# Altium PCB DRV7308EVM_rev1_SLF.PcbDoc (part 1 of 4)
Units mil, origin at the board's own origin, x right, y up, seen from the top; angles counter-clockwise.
Board outline 6187 x 6000 mil, 4 copper layers (Top Layer, Ground, Power, Bottom Layer), stack 61.2 mil thick; 306 components, 128 nets, 676 pads, 1026 vias.
Unrouted connection lines stored in the file: 208.
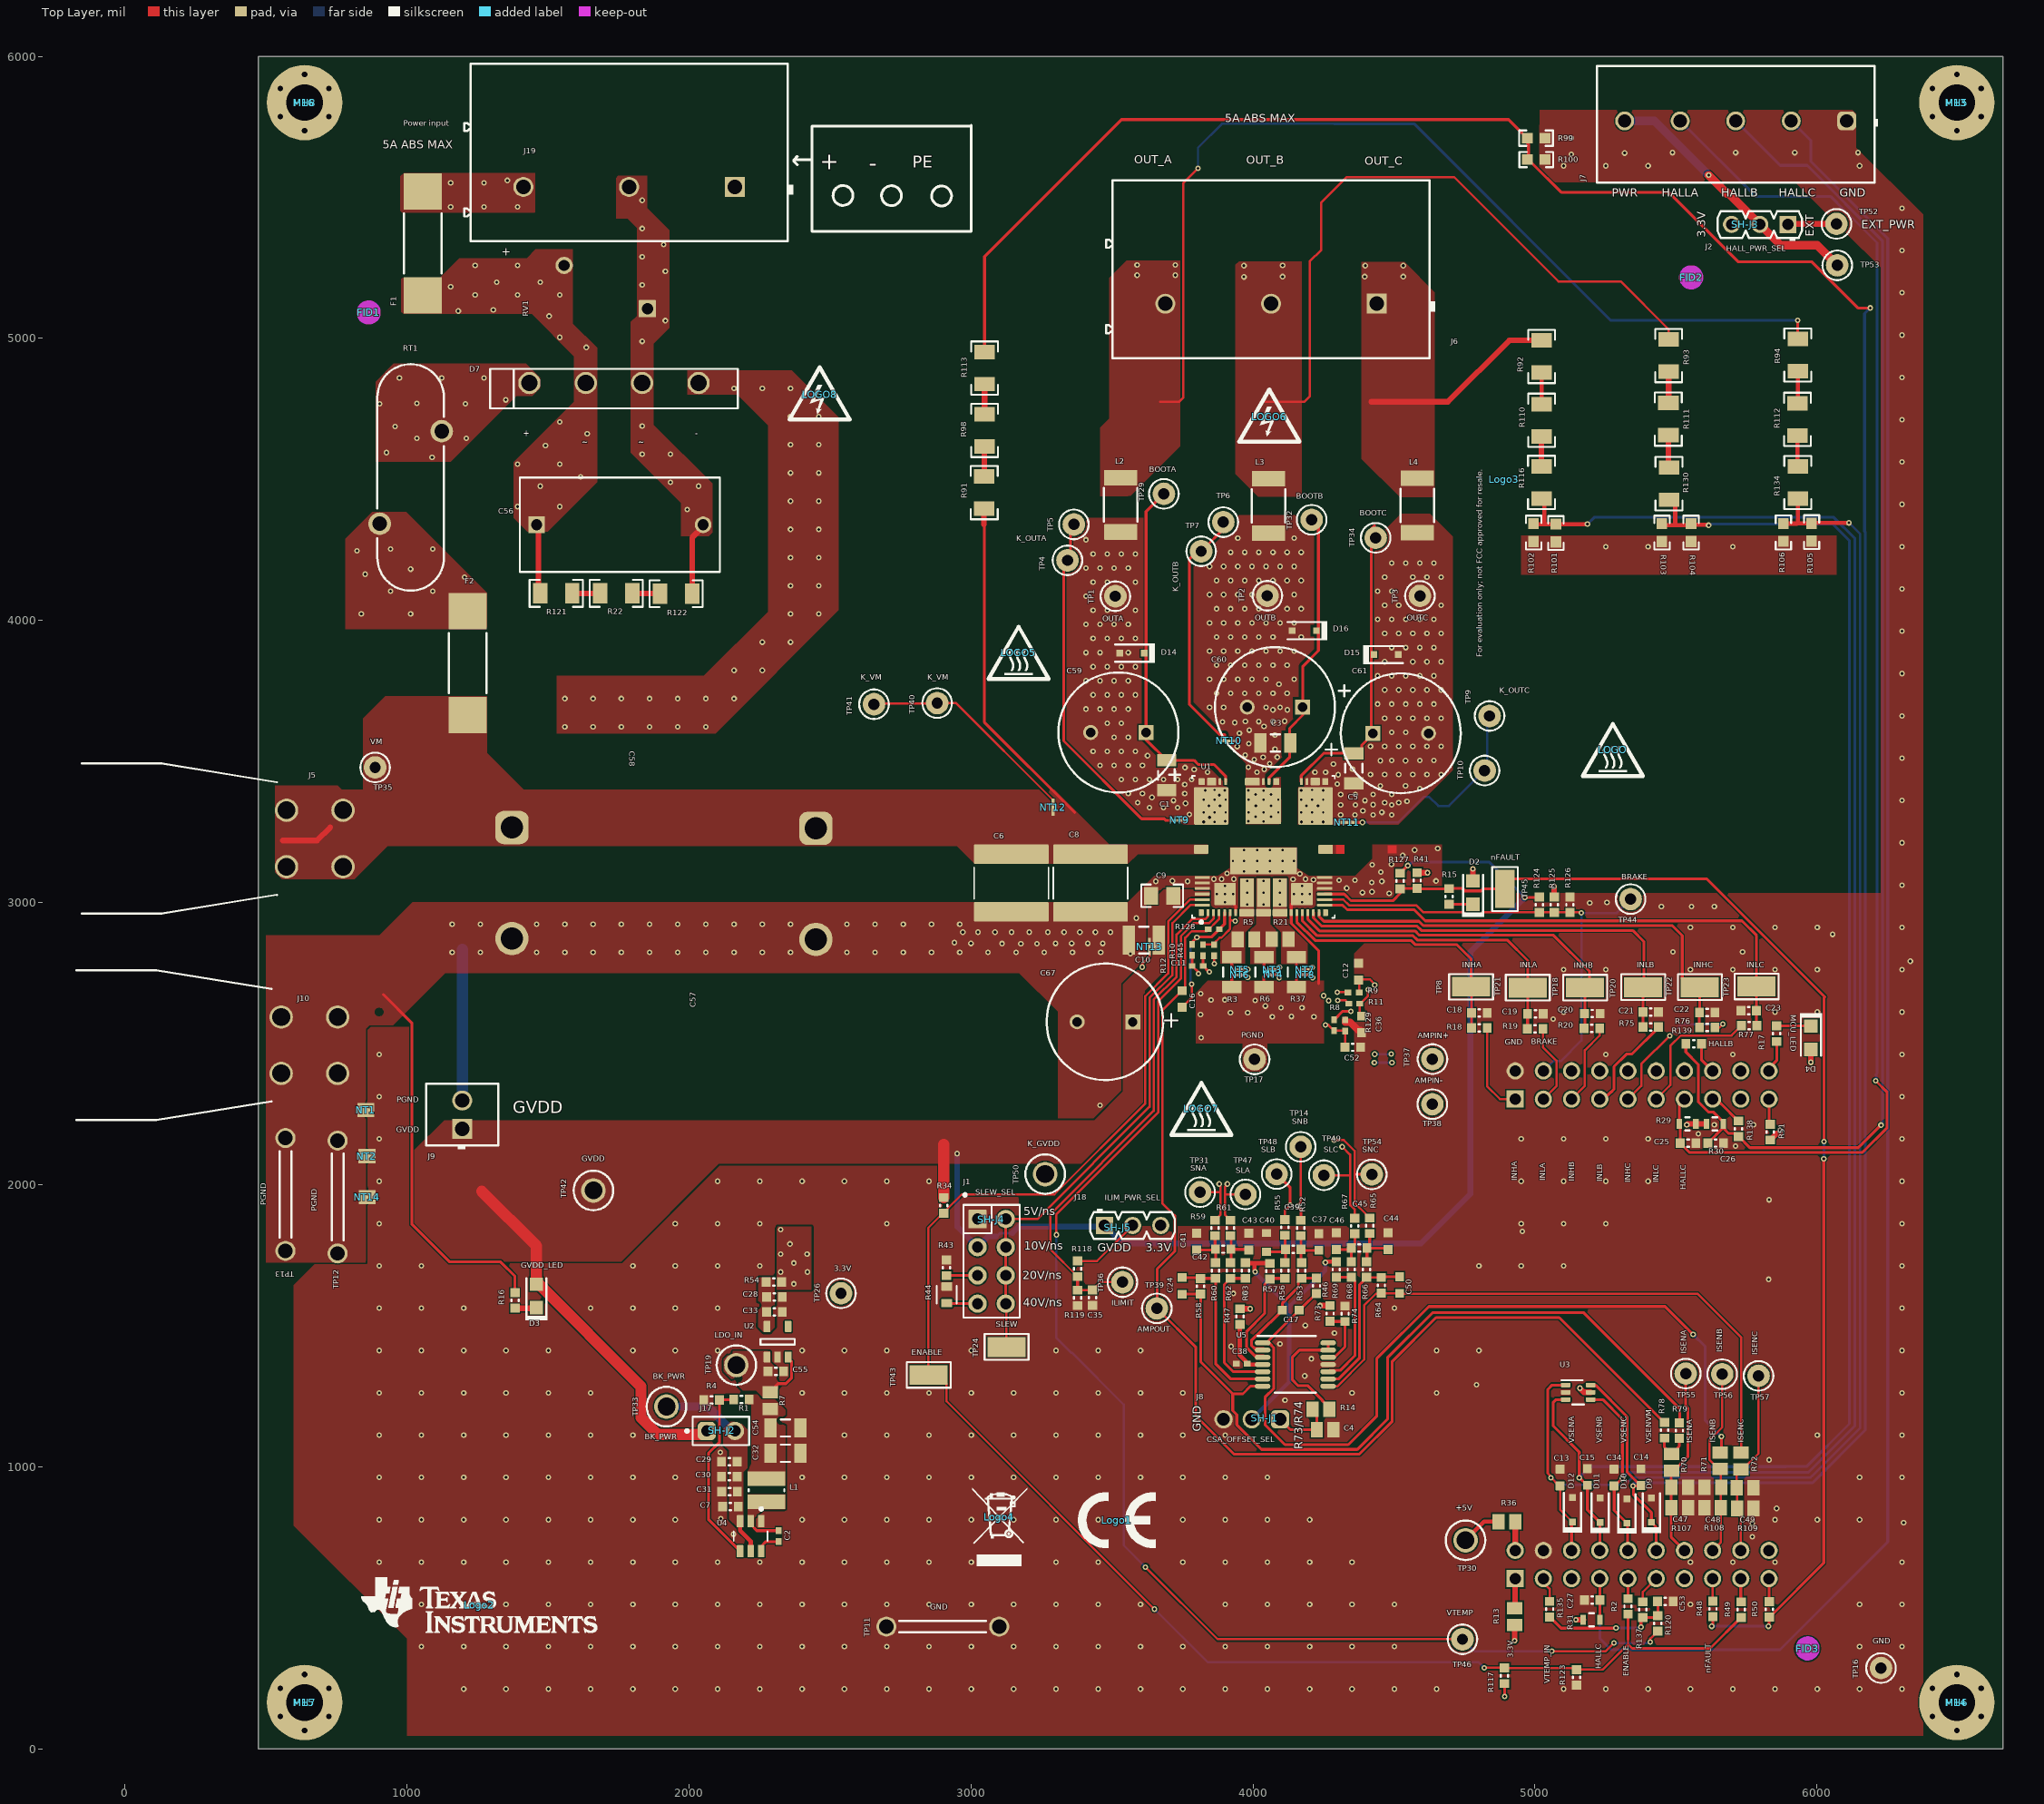
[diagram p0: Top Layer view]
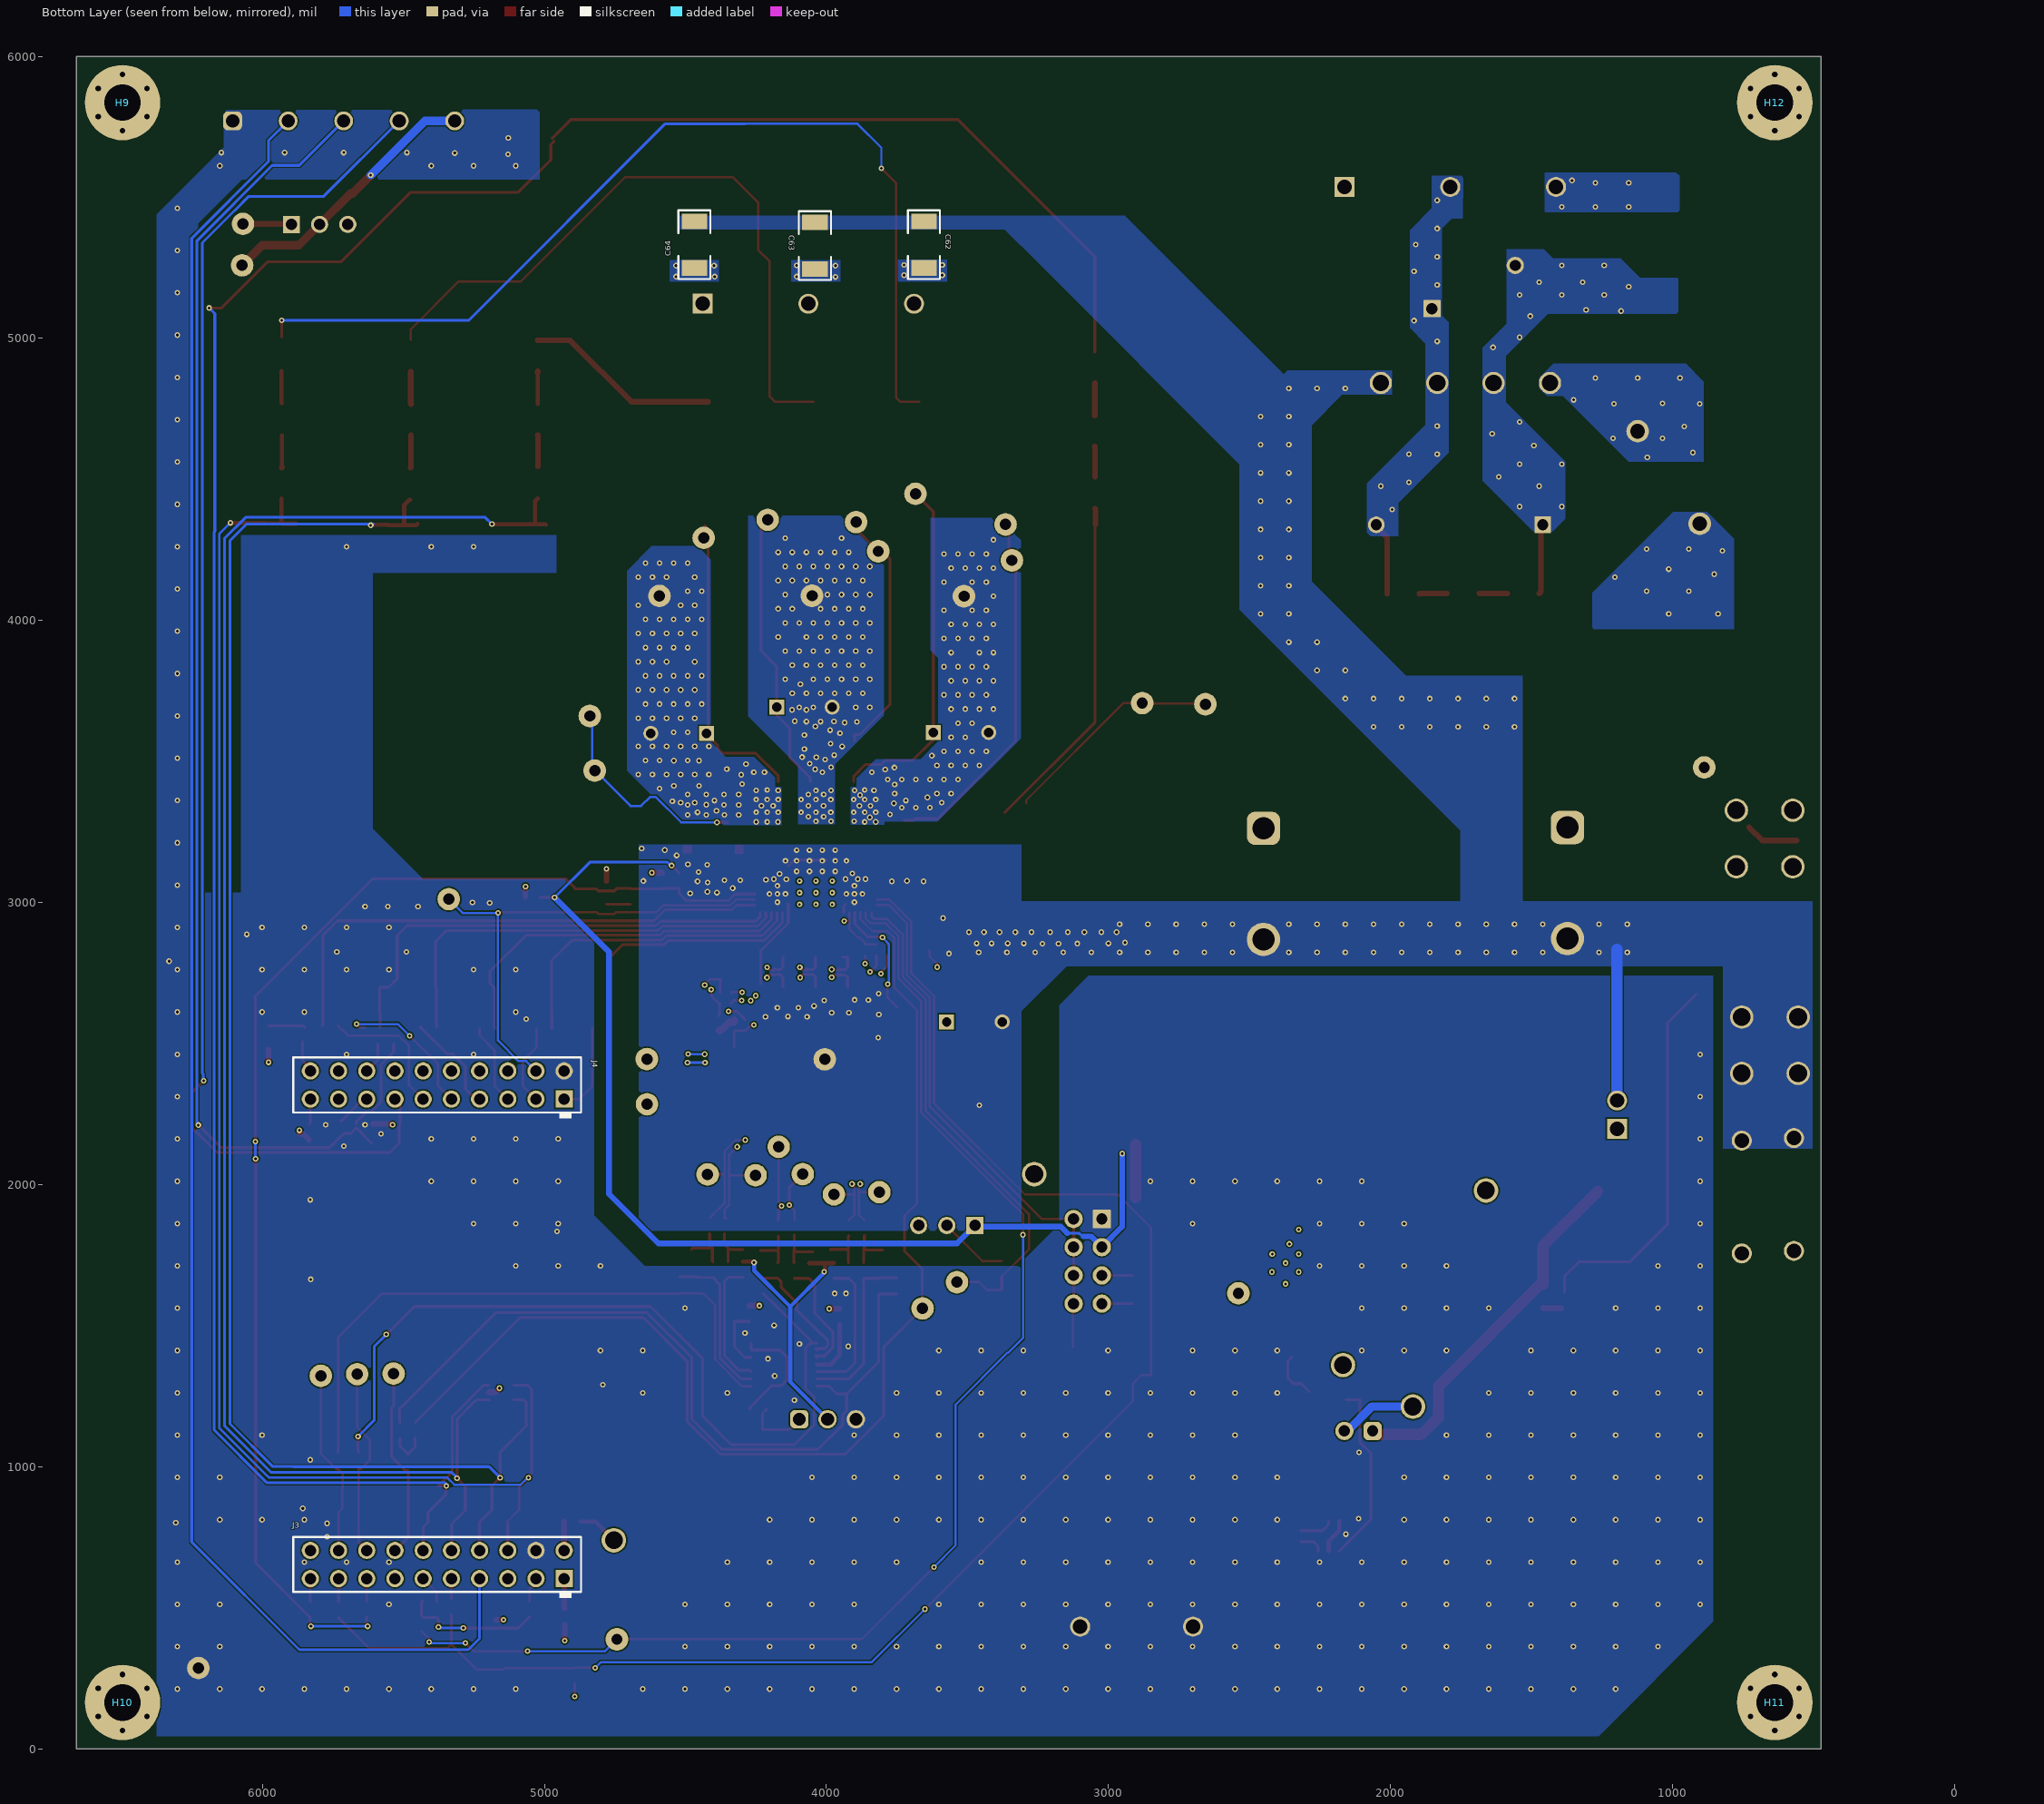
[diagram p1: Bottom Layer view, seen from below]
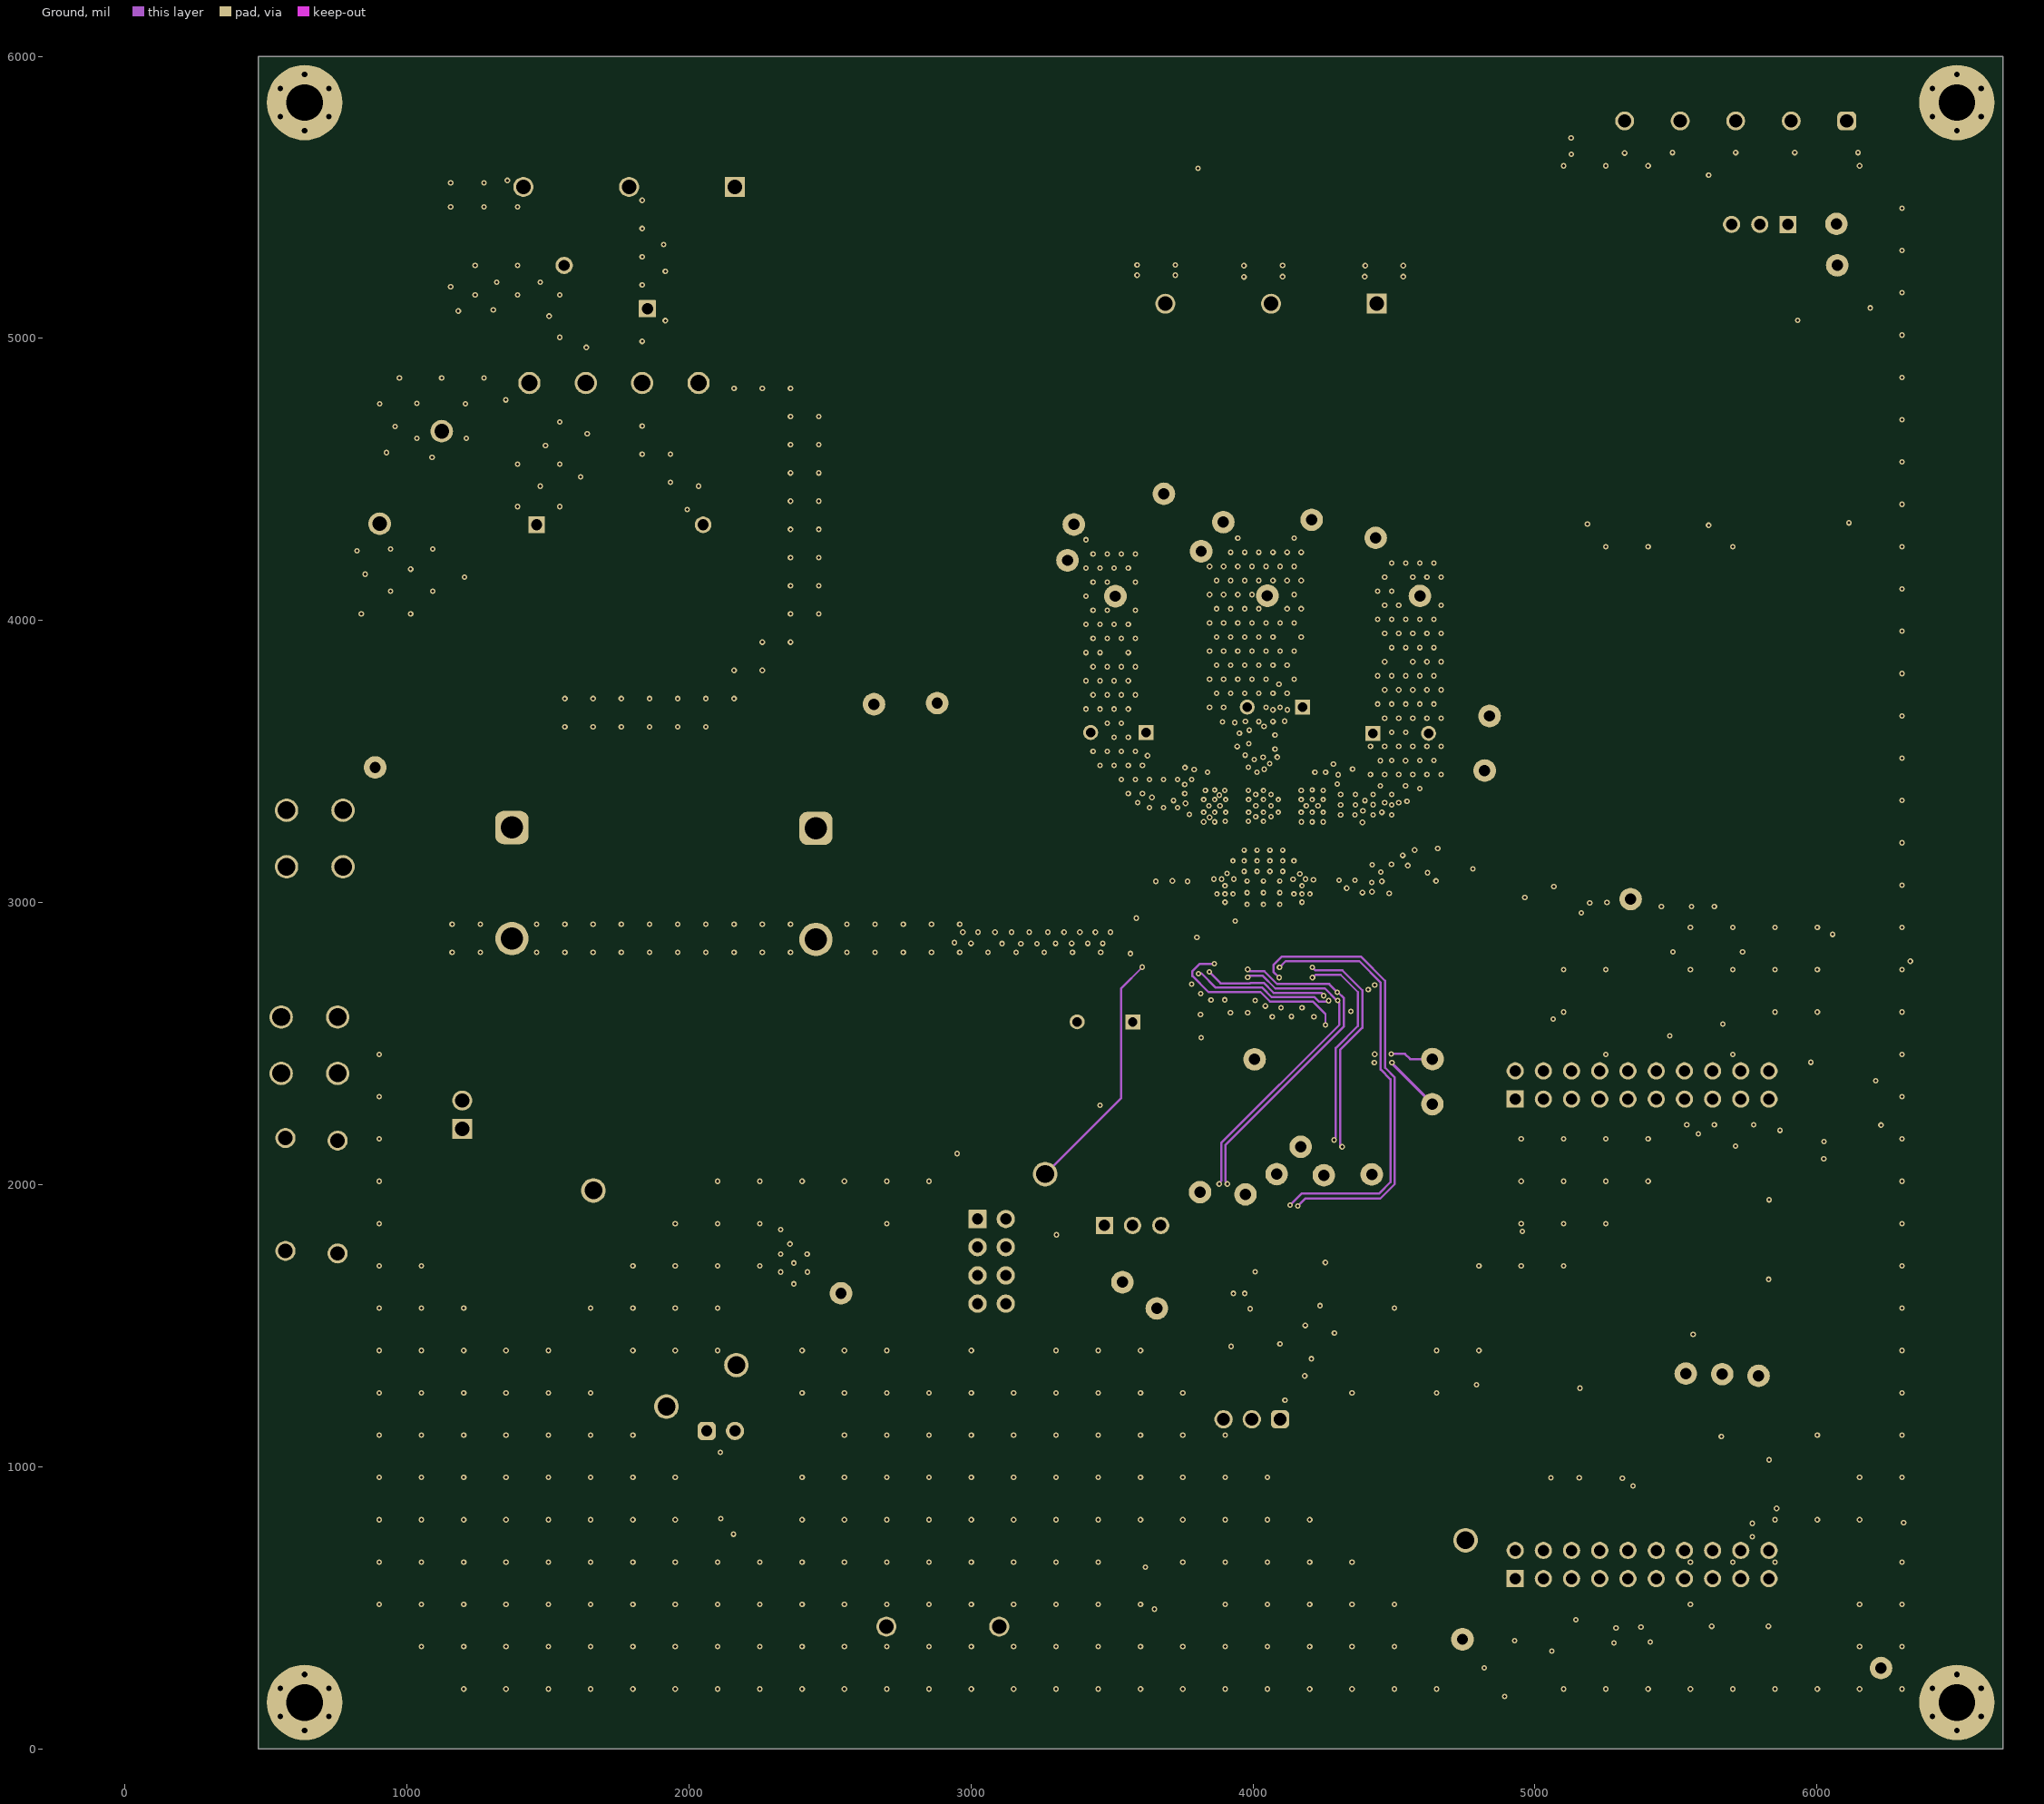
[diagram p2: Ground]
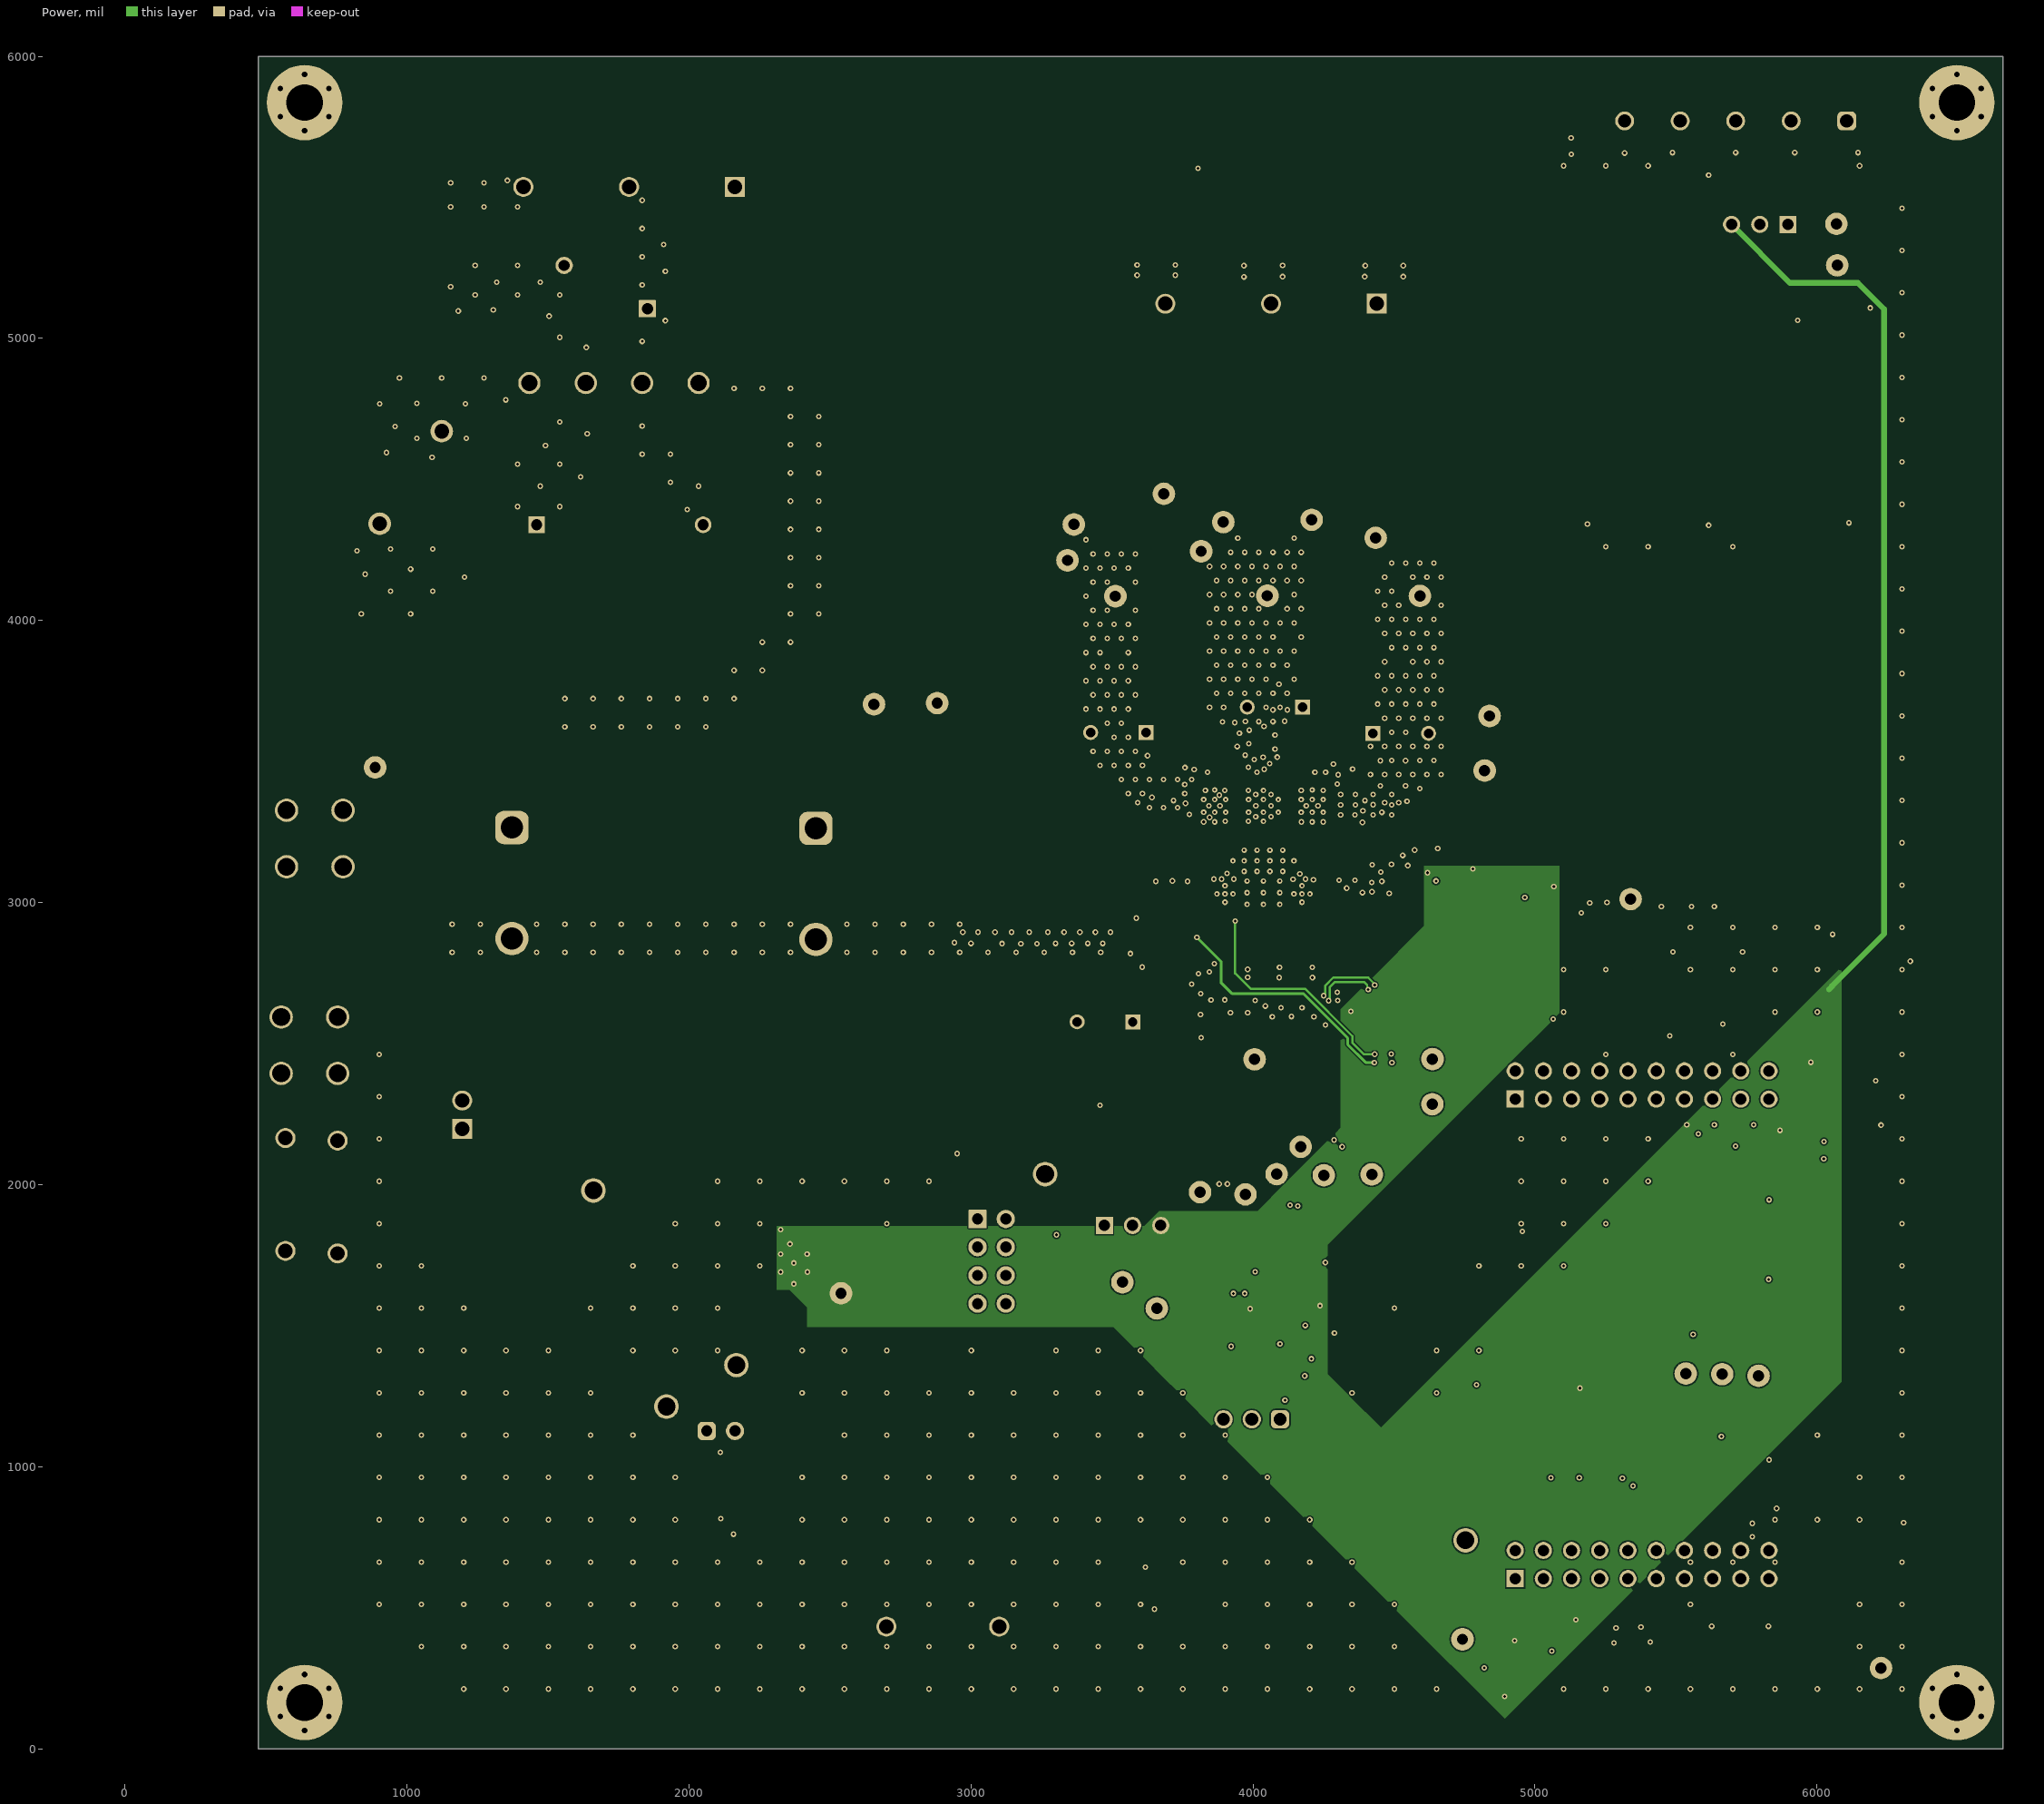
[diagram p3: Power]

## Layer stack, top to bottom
Top Solder: solder mask 0.4, Solder Resist, Dk 3.5
Top Layer: signal copper 4.2
Dielectric 1: prepreg 8, FR-4 High Tg, Dk 4.2
Ground: signal copper 1.4
Dielectric 2: core 34, FR-4 High Tg, Dk 4.2
Power: signal copper 1.4
Dielectric 3: prepreg 8, FR-4 High Tg, Dk 4.2
Bottom Layer: signal copper 4.2
Bottom Solder: solder mask 0.4, Solder Resist, Dk 3.5

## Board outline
473,0 6660,0 6660,6000 473,6000

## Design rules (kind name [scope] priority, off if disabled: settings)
AcuteAngle [All] p1: minimum=4.50000000000000E+0001 checktracksonly=FALSE
AssemblyTestPointUsage [All] p1: valid=2
BoardOutlineClearance BoardOutlineClearance_MountingHoles [OnCopper and InComponentClass('Mounting Holes')] p1: gap=39.37 ignorepadtopadclearanceinfootprint=FALSE
BoardOutlineClearance BoardOutlineClearance_Poly [OnCopper and IsPoly] p2: gap=25 ignorepadtopadclearanceinfootprint=FALSE
BoardOutlineClearance [OnCopper and Not InComponentClass('Logo') and not InComponentClass('FiducialMark') and not InRegion(1000,500,4000,800) and not InPoly] p3: gap=30 ignorepadtopadclearanceinfootprint=FALSE
Clearance Clearance_3 [InNamedPolygon('TOP_LAYER_OUTB_P018')] p1: gap=10 ignorepadtopadclearanceinfootprint=TRUE except(0: Arc-Hole Track-Hole SMDPad-Hole THPad-Hole Via-Hole Fill-Hole Poly-Hole Region-Hole Text-Hole)
Clearance "Stitching AGND" [IsStitchingVia and InNet('AGND') vs (IsVia and (Not IsStitchingVia)) Or IsPad] p2: gap=70 ignorepadtopadclearanceinfootprint=TRUE
Clearance Clearance_Keepouts [((IsTrack Or IsArc) And Not InPoly) And IsFree and IsKeepOut vs ((IsTrack Or IsArc) And Not InPoly) And IsFree and IsKeepOut] p3: gap=7 ignorepadtopadclearanceinfootprint=TRUE
Clearance Clearance_Poly [InPolygon] p4: gap=5 ignorepadtopadclearanceinfootprint=TRUE except(7: Fill-Fill Fill-Poly Fill-Region Poly-Poly Poly-Region Region-Region)
Clearance Clearance_FiducialMark [IsKeepOut and InComponentClass('FiducialMark') vs IsPad and InComponentClass('FiducialMark')] p5: gap=0 ignorepadtopadclearanceinfootprint=FALSE
Clearance [InNetClass('All Nets') vs OnLayer('Top Layer')] p6: gap=7 ignorepadtopadclearanceinfootprint=TRUE
Clearance Clearance_2 [InNetClass('All Nets') vs OnLayer('Bottom Layer')] p7: gap=9 ignorepadtopadclearanceinfootprint=TRUE
Clearance Clearance_1 [InNetClass('All Nets') vs OnLayer('Power')] p8: gap=7.46 ignorepadtopadclearanceinfootprint=TRUE
Clearance Clearance_4 [InNetClass('All Nets') vs OnLayer('Ground')] p9: gap=7.46 ignorepadtopadclearanceinfootprint=TRUE
ComponentClearance ComponentClearance_MountingHoles_FiducialMarks [InComponentClass('Mounting Holes') vs InComponentClass('FiducialMark')] p1: gap=50 collisioncheckmode=3 verticalgap=10 showdistances=FALSE
ComponentClearance ComponentClearance_Shunt [InComponentClass('Header') vs InComponentClass('Shunt')] p2: gap=0 collisioncheckmode=3 verticalgap=0 showdistances=FALSE
ComponentClearance ComponentClearance_Logo [InComponentClass('Logo')] p3: gap=50 collisioncheckmode=3 verticalgap=10 showdistances=FALSE
ComponentClearance ComponentClearance_ScrewToNut [(HasFootprint('NY PMS 440 0025 PH')) vs (HasFootprint('Keystone_1902C'))] p4: gap=5 collisioncheckmode=3 verticalgap=10 showdistances=FALSE
ComponentClearance ComponentClearance_MountingHoles [InComponentClass('Mounting Holes')] p5: gap=250 collisioncheckmode=3 verticalgap=100000 showdistances=FALSE
ComponentClearance ComponentClearance_SmallPassives [HasFootprint('0201*') or HasFootprint('0402*') or HasFootprint('0508') or HasFootprint('0603*') or HasFootprint('0612') or HasFootprint('0805*') or HasFootprint('0815*') or HasFootprint('0830*') or HasFootprint('1206*') or HasFootprint('1210*') or HasFootprint('1808*') or HasFootprint('1812*') or HasFootprint('1825*') or HasFootprint('2010*') or HasFootprint('2220*') or HasFootprint('2225*') or HasFootprint('2512*') or HasFootprint('2728*') or HasFootprint('3518*') vs HasFootprint('0201*') or HasFootprint('0402*') or HasFootprint('0508') or HasFootprint('0603*') or HasFootprint('0612') or HasFootprint('0805*') or HasFootprint('0815*') or HasFootprint('0830*') or HasFootprint('1206*') or HasFootprint('1210*') or HasFootprint('1808*') or HasFootprint('1812*') or HasFootprint('1825*') or HasFootprint('2010*') or HasFootprint('2220*') or HasFootprint('2225*') or HasFootprint('2512*') or HasFootprint('2728*') or HasFootprint('3518*')] p6: gap=14.96 collisioncheckmode=3 verticalgap=10 showdistances=FALSE
ComponentClearance ComponentClearance_THtoSMT [IsThruComponent vs IsSMTComponent] p7: gap=40 collisioncheckmode=3 verticalgap=30 showdistances=FALSE
ComponentClearance ComponentClearance_THtoTH [IsThruComponent vs IsThruComponent] p8: gap=30 collisioncheckmode=3 verticalgap=30 showdistances=FALSE
ComponentClearance [All] p9: gap=30 collisioncheckmode=3 verticalgap=10 showdistances=FALSE
ComponentClearance ComponentClearance_NT [(InComponent('NT1') OR InComponent('NT2') OR InComponent('NT3') OR InComponent('NT4') OR InComponent('NT5') OR InComponent('NT6')) vs InComponent('No Component')] p10: gap=0 collisioncheckmode=3 verticalgap=10 showdistances=FALSE
DiffPairsRouting [All] p1: maxlimit=100 minlimit=10 mostfreqgap=10 toplayer_minwidth=15 toplayer_maxwidth=15 toplayer_prefwidth=15 midlayer1_minwidth=15 midlayer1_maxwidth=15 midlayer1_prefwidth=15 midlayer2_minwidth=15 midlayer2_maxwidth=15 midlayer2_prefwidth=15 bottomlayer_minwidth=15 bottomlayer_maxwidth=15 bottomlayer_prefwidth=15 maxuncoupledlength=1000
FabricationTestPointUsage TestPointUsage [All] p1: valid=2 allowmultiple=FALSE
FabricationTestpoint Testpoint [All] p1: side=3 testpointundercomponent=TRUE minsize=40 maxsize=100 preferedsize=60 minholesize=0 maxholesize=40 preferedholesize=32 testpointgrid=1 allowsidetop=TRUE allowsidebottom=TRUE usegrid=TRUE gridtolerance=0.01
FanoutControl Fanout_LCC [IsLCC] p1: bgadir=Out bgaviamode=Centered fanoutstyle=Auto fanoutdirection=Alternating viagrid=1 // Fanout_LCC (Default Rule)
FanoutControl Fanout_BGA [IsBGA] p2: bgadir=Out bgaviamode=Centered fanoutstyle=Auto fanoutdirection=Alternating viagrid=1 // Fanout_BGA (Default Rule)
FanoutControl Fanout_Default [All] p4: bgadir=Out bgaviamode=Centered fanoutstyle=Auto fanoutdirection=Alternating viagrid=1 // Fanout_Default (Default Rule)
FanoutControl Fanout_Small [(CompPinCount < 5)] p5: bgadir=Out bgaviamode=Centered fanoutstyle=Auto fanoutdirection=OutThenIn viagrid=1 // Fanout_Small (Default Rule)
Height [All] p1: minheight=0 maxheight=1270 prefheight=500
HoleSize [All] p1: absolutevalues=TRUE maxlimit=270 minlimit=1 maxpercent=80.000 minpercent=20.000
MinimumAnnularRing MinimumAnnularRing_ThermalPadVias [IsVia and InAnyComponent] p1: minimumring=5
MinimumAnnularRing [All] p2: minimumring=5
MinimumSolderMaskSliver MinimumSolderMaskSliver_Logo [InComponentClass('Logo') vs InComponentClass('Logo')] p1: minsoldermaskwidth=0.7
MinimumSolderMaskSliver [All] p2: minsoldermaskwidth=1
PlaneConnect [All] p1: planeconnectstyle=Direct reliefexpansion=10 reliefentries=4 reliefconductorwidth=10 reliefairgap=10
PolygonConnect "direct connect OUTB" [All vs IsNamedPolygon('TOP_LAYER_OUTB_P018')] p1: connectstyle=Direct reliefconductorwidth=10 reliefentries=4 polygonreliefangle="90 Angle" airgapwidth=10
PolygonConnect OUTB_POLY [All vs IsNamedPolygon('TOP_LAYER_OUTB_P018')] p2: connectstyle=Direct reliefconductorwidth=10 reliefentries=4 polygonreliefangle="90 Angle" airgapwidth=10
PolygonConnect PolygonConnect_1 [All vs IsNamedPolygon('TOP_LAYER_OUTB_P018')] p3: connectstyle=Direct reliefconductorwidth=10 reliefentries=4 polygonreliefangle="90 Angle" airgapwidth=10
PolygonConnect [All] p4: connectstyle=Direct reliefconductorwidth=10 reliefentries=4 polygonreliefangle="90 Angle" airgapwidth=10
RoutingVias ThermalPadVias [IsVia and InAnyComponent] p1: holewidth=7.87 width=19.68 viastyle="Through Hole" minholewidth=7.87 minwidth=19.68 maxholewidth=30 maxwidth=50
RoutingVias [All] p2: holewidth=10 width=25 viastyle="Through Hole" minholewidth=10 minwidth=20 maxholewidth=10 maxwidth=30
SilkToBoardRegionClearance [Not ((IsComment or IsDesignator) And (Hide <> 'False')) and not InRegion(1000,500,4000,800)] p1:
SilkToSilkClearance SilkToSilkClearance_Pb-FreeLogo [(HasFootprint('Pb-Free_Overlay_Medium') OR HasFootprint('Pb-Free_Overlay_Small')) vs (HasFootprint('Pb-Free_Overlay_Medium') OR HasFootprint('Pb-Free_Overlay_Small'))] p1: silktosilkclearance=1
SilkToSilkClearance [All] p2: silktosilkclearance=1
SilkToSolderMaskClearance [IsPad] p1: minsilkscreentomaskgap=1 clearancetoexposedcopper=TRUE
SolderMaskExpansion [All] p1: expansion=1.97 istentingtop=FALSE
UnRoutedNet [All] p1: checkbadconnections=TRUE
Width [All] p1: maxlimit=100 minlimit=6 preferedwidth=10 checkconnectedcopper=TRUE
13 further rules are at their usual default settings.

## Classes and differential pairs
component class Screw: H13 H14 H15 H16
net class High_Voltage: OUTA OUTC VM
component class DRV7308EVM_rev1_POWER_AND_CONNECTORS_SLF: C4 C13 C14 C15 C17 C24 C25 C26 C27 C34 C35 C37 C38 C39 C40 C41 C42 C43 C44 C45 C46 C47 C48 C49 C50 C56 C57 C58 C62 C63 C64 D7 D9 D10 D11 D12 F1 F2 HALL_PWR J1 J2 J5 J6 J7 J8 J9 J10 J18 J19 L2 L3 L4 NT1 NT2 NT13 NT14 R14 R22 R29 R30 R31 R43 R44 R46 R47 R52 R53 R55 R56 R57 R58 R59 R60 R61 R62 R63 R64 R65 R66 R67 R68 R69 R70 R71 R72 R73 R74 R78 R79 R91 R92 R93 R94 R98 R99 R100 R101 R102 R103 R104 R105 R106 R107 R108 R109 R110 R111 R112 R113 R116 R118 R119 R121 R122 R130 R134 RT1 RV1 SH-J1 SH-J3 SH-J4 SH-J5 TP11 TP12 TP13 TP14 TP16 TP17 TP31 TP42 TP50 TP52 TP53 TP54 TP55 TP56 TP57 U3 U5
component class Shunt: SH-J1 SH-J2 SH-J3 SH-J4 SH-J5
component class DRV7308EVM_rev1_DRIVER_SLF: 40 C1 C2 C3 C5 C6 C7 C8 C9 C10 C11 C12 C16 C18 C19 C20 C21 C22 C23 C28 C29 C30 C31 C32 C33 C36 C52 C53 C54 C55 C59 C60 C61 C67 D2 D3 D4 D14 D15 D16 D? J3 J4 J17 L1 NT3 NT4 NT5 NT6 NT7 NT8 NT9 NT10 NT11 NT12 R1 R2 R3 R4 R5 R6 R7 R8 R9 R10 R11 R12 R13 R15 R16 R17 R18 R19 R20 R21 R34 R36 R37 R41 R45 R48 R49 R50 R51 R54 R75 R76 R77 R117 R120 R123 R124 R125 R126 R127 R128 R129 R135 R137 R138 R139 SH-J2 TP1 TP2 TP3 TP4 TP5 TP6 TP7 TP8 TP9 TP10 TP18 TP19 TP20 TP21 TP22 TP23 TP24 TP26 TP29 TP30 TP32 TP33 TP34 TP35 TP36 TP37 TP38 TP39 TP40 TP41 TP43 TP44 TP45 TP46 TP47 TP48 TP49 U1 U2 U4
component class Header: J1 J2 J8 J17 J18
component class Logo: Logo2
component class DRV7308EVM_rev1_HARDWARE_SLF: FID1 FID2 FID3 H9 H10 H11 H12 H13 H14 H15 H16 LOGO Logo1 Logo2 Logo3 Logo4 LOGO5 LOGO6 LOGO7 LOGO8 MH5 MH6 MH7 MH8 ZZ1 ZZ2 ZZ3 ZZ4
component class FiducialMark: FID1 FID2 FID3
component class AssemblyNote: ZZ1 ZZ2 ZZ3 ZZ4

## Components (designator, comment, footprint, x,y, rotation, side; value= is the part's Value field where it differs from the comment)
C1 "12063C105KAT2A" 1206L 3694,3451 r90 top value=1uF
C2 "CL05B104KP5NNNC" 0402L 2318,753.76 r270 top value=0.1uF
C3 "12063C105KAT2A" 1206L 4079,3566 r0 top value=1uF
C4 "C0805C471K5RACTU" 0805L 4256,1131 r0 top value=470pF
C5 "12063C105KAT2A" 1206L 4357,3476 r90 top value=1uF
C6 "VJ2225Y104KXGAT" FP-VJ2225Y104KXGAT_2225-IPC_A 3143,3069 r90 top value=100nF
C7 "885012206095" 0603L 2147,858.44 r180 top value=0.1uF
C8 "VJ2225Y104KXGAT" FP-VJ2225Y104KXGAT_2225-IPC_A 3424,3068.81 r90 top value=100nF
C9 "08053C104KAT2A" 0805_HV 3678,3024 r0 top value=0.1uF
C10 "GRM32ER71E226KE15L" 1210_270L 3613,2867 r0 top value=22uF
C11 "CL05B103KA5NNNC" 0402L 3804,2775 r180 top value=0.01uF
C12 "885012206003" WCAP-CSGP_0603_L1.6W0.8H0.8_Reflow 4374,2755 r270 top
C13 "885012206069" FP-885012206069_0603-MFG 5089,961.53 r270 top
C14 "885012206069" FP-885012206069_0603-MFG 5376,962.53 r270 top
C15 "885012206069" FP-885012206069_0603-MFG 5186,963.53 r270 top
C16 "885012206003" WCAP-CSGP_0603_L1.6W0.8H0.8_Reflow 3749,2658 r90 top
C17 "885012206003" WCAP-CSGP_0603_L1.6W0.8H0.8_Reflow 4134,1555 r0 top
C18 "885012206083" 0603L 4802.59,2608.59 r0 top value=1000pF
C19 "885012206083" 0603L 5001.36,2605.29 r0 top value=1000pF
C20 "885012206083" 0603L 5203.36,2606.29 r0 top value=1000pF
C21 "885012206083" 0603L 5410.59,2611.59 r0 top value=1000pF
C22 "885012206083" 0603L 5610.59,2609.59 r0 top value=1000pF
C23 "885012206083" 0603L 5757.61,2616.59 r180 top value=1000pF
C24 "885012206003" WCAP-CSGP_0603_L1.6W0.8H0.8_Reflow 3749,1641 r270 top
C25 "885012206034" 0603L 5542.82,2147 r0 top value=1000pF
C26 "885012206034" 0603L 5640.82,2147 r0 top value=1000pF
C27 "885012206034" 0603L 5202.82,527 r180 top value=1000pF
C28 "LMK107B7105KAHT" 0603L 2303,1601.44 r0 top value=1uF
C29 "CGA3E1X7R1E105K080AC" 0603L 2143,1017.44 r180 top value=1uF
C30 "CGA3E1X7R1E105K080AC" 0603L 2143,964.44 r180 top value=1uF
C31 "CGA3E1X7R1E105K080AC" 0603L 2144,911.44 r180 top value=1uF
C32 "C3216X7R1E106K160AB" 1206_180L 2342,1047.44 r0 top value=10uF
C33 "EMK107B7104KA-T" 0603L 2303,1548.44 r0 top value=0.1uF
C34 "885012206069" FP-885012206069_0603-MFG 5280,961.53 r270 top
C35 "885012206095" 0603L 3431,1599 r270 top value=0.1uF
C36 "885012206003" WCAP-CSGP_0603_L1.6W0.8H0.8_Reflow 4385,2568 r270 top
C37 "885012206003" WCAP-CSGP_0603_L1.6W0.8H0.8_Reflow 4234,1796.53 r270 top
C38 "C1005X5R1A225K050BC" 0402L 3960.26,1365.14 r0 top value=2.2uF
C39 "885012206034" 0603L 4142.56,1770 r180 top value=1000pF
C40 "885012206003" WCAP-CSGP_0603_L1.6W0.8H0.8_Wave 4048.26,1795.14 r90 top
C41 "885012206003" WCAP-CSGP_0603_L1.6W0.8H0.8_Reflow 3800,1798 r270 top
C42 "885012206034" 0603L 3894.26,1771.14 r0 top value=1000pF
C43 "885012206003" WCAP-CSGP_0603_L1.6W0.8H0.8_Reflow 3985,1798 r90 top
C44 "885012206003" WCAP-CSGP_0603_L1.6W0.8H0.8_Reflow 4479,1799.53 r270 top
C45 "885012206034" 0603L 4376.56,1775 r180 top value=1000pF
C46 "885012206003" WCAP-CSGP_0603_L1.6W0.8H0.8_Reflow 4296,1799.53 r90 top
C47 "C0805C471K5RACTU" 0805L 5512.82,927 r0 top value=470pF
C48 "C0805C471K5RACTU" 0805L 5630.82,927 r180 top value=470pF
C49 "C0805C471K5RACTU" 0805L 5744.82,925 r0 top value=470pF
C50 "885012206003" WCAP-CSGP_0603_L1.6W0.8H0.8_Reflow 4520,1644 r270 top
C52 "885012206095" 0603L 4354,2487 r180 top value=0.1uF
C53 "06031C103JAT2A" 0603L 5462.14,521.69 r0 top value=0.01uF
C54 "C3216X7R1E106K160AB" 1206_180L 2342,1137.44 r0 top value=10uF
C55 "LMK107B7105KAHT" 0603L 2308,1337.9 r0 top value=1uF
C56 "B32922C3334M" B32922_14.5mm 1755,4339.36 r0 top value=0.33uF
C57 "381LQ151M450J022" 381LQ_J02 2450.24,3066.15 r270 top value=150uF
C58 "381LQ151M450J022" 381LQ_J02 1372,3069 r270 top value=150uF
C59 "UBT1E221MPD1TD" BT_1000x1250 3522.57,3603 r180 top value=220uF
C60 "UBT1E221MPD1TD" BT_1000x1250 4078,3693 r180 top value=220uF
C61 "UBT1E221MPD1TD" BT_1000x1250 4524,3600 r0 top value=220uF
C62 "GR442QR73D102KW01L" 1808 3654,5332.32 r90 bottom value=1000pF
C63 "GR442QR73D102KW01L" 1808 4040.9,5329 r90 bottom value=1000pF
C64 "GR442QR73D102KW01L" 1808 4468,5332.32 r90 bottom value=1000pF
C67 "EKMG250ELL102MJ20S" Chemi-Con_1000x2000 3475,2577 r180 top value=1000uF
D2 "LTST-C170KRKT" LED_LTST-C170_Red 4780,3035.42 r270 top value=Red
D3 "GVDD_LED" LTST-C170KGKT_Green 1459,1605.34 r270 top value=Green
D4 "MCU_LED" LTST-C170KFKT_Orange 5978.28,2520.42 r90 top value=Orange
D7 "GBU606" GBU 1734,4842 r0 top value=600V
D9 "MMDL101T1G" SOD-323 5412.82,846 r90 top value=7V
D10 "MMDL101T1G" SOD-323 5325.82,843 r90 top value=7V
D11 "MMDL101T1G" SOD-323 5230.82,845.31 r90 top value=7V
D12 "MMDL101T1G" SOD-323 5132.82,847 r90 top value=7V
D14 "MMSZ5248BS-7-F" SOD-323 3570.69,3884 r180 top value=18V
D15 "MMSZ5248BS-7-F" SOD-323 4472.31,3879 r0 top value=18V
D16 "MMSZ5248BS-7-F" SOD-323 4181.69,3964 r180 top value=18V
F1 "0443003.DR" FUSE_0443 1056,5337 r90 top
F2 "0443003.DR" FUSE_0443 1215,3849 r270 top
FID1 "Fiducial" Fiducial10-20 864,5092 r0 top
FID2 "Fiducial" Fiducial10-20 5553.69,5216.5 r0 top
FID3 "Fiducial" Fiducial10-20 5966.33,355.55 r0 top
H9 "24438" Keystone24438 6496,5836 r180 bottom
H10 "24438" Keystone24438 6496,164 r180 bottom
H11 "24438" Keystone24438 637,164 r180 bottom
H12 "24438" Keystone24438 637,5836 r180 bottom
H13 "MPMS 003 0005 PH" BuildingFastener_MPMS_003_0005_PH 6496,5836 r0 top
H14 "MPMS 003 0005 PH" BuildingFastener_MPMS_003_0005_PH 6496,164 r0 top
H15 "MPMS 003 0005 PH" BuildingFastener_MPMS_003_0005_PH 637,164 r0 top
H16 "MPMS 003 0005 PH" BuildingFastener_MPMS_003_0005_PH 637,5836 r0 top
J1 "SLEW_SEL" TSW-104-07-G-D 3073.23,1728 r270 top
J2 "HALL_PWR_SEL" FCI_68001-403HLF 5797,5404 r180 top
J3 "SSQ-110-03-G-D" Samtec_SSQ-110-03-x-D 5379.82,653 r0 bottom
J4 "SSQ-110-03-G-D" Samtec_SSQ-110-03-x-D 5379.82,2353 r0 bottom
J5 "CT3151SP-2" CTE_CT3151SP-2 -171,3227 r0 top
J6 "1904150" Phoenix_1904150 4064,5245 r180 top
J7 "HALL IN" Phoenix_1792892 5711.74,5771 r180 top
J8 "CSA_OFFSET_SEL" WURTH_61300311121 3995.7,1168 r180 top
J9 "GVDD" On-Shore_OSTVN02A150 1196,2248 r90 top
J10 "CT3151SP-0" CTE_CT3151SP-0 -190,2494 r0 top
J17 "BK_PWR" TSW-102-07-G-S 2113,1126.44 r0 top
J18 "ILIM_PWR_SEL" FCI_68001-403HLF 3573,1855 r0 top
J19 "Power input" Phoenix_1904150 1787.5,5659 r180 top
L1 "78438335047" WE-MAIA_3015 2275,916.44 r90 top value=4.7uH
L2 "742792511" 1812_170_HighSpeed 3531,4410 r90 top value="120 ohm"
L3 "742792511" 1812_170_HighSpeed 4055,4406 r90 top value="120 ohm"
L4 "742792511" 1812_170_HighSpeed 4583,4408 r90 top value="120 ohm"
LOGO "CAUTION HOT SURFACE" IEC_HotSurface_Small 5276,3541 r0 top
Logo1 "CE Mark" CE_Mark_5mm 3517,810 r0 top
Logo2 "Texas Instruments" TI_Stacked_Overlay_Small 1256,509 r0 top
Logo3 "FCC disclaimer" FCC_disclaimer 4890,4499.8 r90 top
Logo4 "WEEE logo" WEEE_Minimum 3100,820.64 r0 top
LOGO5 "CAUTION HOT SURFACE" IEC_HotSurface_Small 3169,3886 r0 top
LOGO6 "DANGER HIGH VOLTAGE" IEC_HighVoltage_Small 4058,4722 r0 top
LOGO7 "CAUTION HOT SURFACE" IEC_HotSurface_Small 3817,2269 r0 top
LOGO8 "DANGER HIGH VOLTAGE" IEC_HighVoltage_Small 2463.51,4800.51 r0 top
MH5 "MTG_Pads" MTGP_M3_PanHead 6496,5836 r0 top
MH6 "MTG_Pads" MTGP_M3_PanHead 6496,164 r0 top
MH7 "MTG_Pads" MTGP_M3_PanHead 637,164 r0 top
MH8 "MTG_Pads" MTGP_M3_PanHead 637,5836 r0 top
NT1 "Net-Tie" Net-Tie_50milWide_30milLong 854,2263.85 r180 top net-tie
NT2 "Net-Tie" Net-Tie_50milWide_30milLong 858,2101 r180 top net-tie
NT3 "Net-Tie" Net-Tie_10mil 4070,2762 r0 top net-tie
NT4 "Net-Tie" Net-Tie_10mil 4073,2745 r0 top net-tie
NT5 "Net-Tie" Net-Tie_10mil 3954,2762 r0 top net-tie
NT6 "Net-Tie" Net-Tie_10mil 3954,2743 r0 top net-tie
NT7 "Net-Tie" Net-Tie_10mil 4186,2762 r0 top net-tie
NT8 "Net-Tie" Net-Tie_10mil 4186,2744 r0 top net-tie
NT9 "Net-Tie" Net-Tie_10milWide_30milLong 3740,3292 r180 top net-tie
NT10 "Net-Tie" Net-Tie_10milWide_30milLong 3915,3573 r180 top net-tie
NT11 "Net-Tie" Net-Tie_10milWide_30milLong 4334,3284 r0 top net-tie
NT12 "Net-Tie" Net-Tie_10milWide_30milLong 3291,3338 r270 top net-tie
NT13 "Net-Tie" Net-Tie_10milWide_30milLong 3633,2844 r90 top net-tie
NT14 "Net-Tie" Net-Tie_50milWide_30milLong 859,1956 r180 top net-tie
R1 "CRCW0603162KFKEA" 0603L 2186,1237.44 r0 top value=162k
R2 "ERJ-3GEY0R00V" 0603L 5329.93,504.56 r90 top value=0
R3 "CSR1206FK30L0" 1206L 3925,2753 r90 top value=0.03
R4 "RT0603DRE0722K1L" 0603L 2080,1236.44 r0 top value=22.1k
R5 "ERJ-6GEY0R00V" 0805L 3975,2869 r180 top value=0
R6 "CSR1206FK30L0" 1206L 4038.82,2753 r90 top value=0.03
R7 "ERJ-6GEY0R00V" 0805L 2288,1234.44 r90 top value=0
R8 "CRCW040220K0FKED" 0402L 4288,2565 r90 top value=20.0k
R9 "CRCW040210R2FKED" 0402L 4356.68,2681 r0 top value=10.2
R10 "ERJ-2RKF2001X" 0402L 3823,2831 r90 top value=2.00k
R11 "CRCW040210R2FKED" 0402L 4359,2642 r0 top value=10.2
R12 "ERJ-2RKF2001X" 0402L 3784,2832 r90 top value=2.00k
R13 "ERJ-6GEY0R00V" 0805L 4927.82,468.6 r90 top value=0
R14 "CRCW0805330RFKEAC" 0805L 4241,1204 r180 top value=330
R15 "ERA3AEB331V" 0603L 4695,3021.42 r270 top value=330
R16 "RT0603BRD074K7L" 0603L 1383,1589.44 r270 top value=4.70k
R17 "ERA3AEB331V" 0603L 5857.19,2535.03 r90 top value=330
R18 "RC0603FR-07100RL" 0603L 4802.59,2555.59 r180 top value=100
R19 "RC0603FR-07100RL" 0603L 5000.59,2552.59 r180 top value=100
R20 "RC0603FR-07100RL" 0603L 5201.59,2553.59 r180 top value=100
R21 "ERJ-6GEY0R00V" 0805L 4096.13,2870 r180 top value=0
R22 "RC1206FR-07330KL" 1206 1742,4096 r180 top value=330k
R29 "TNPW060310K0BEEA" TNPW0603 5540.82,2215 r0 top value=10.0k
R30 "TNPW060310K0BEEA" TNPW0603 5637.82,2215 r180 top value=10.0k
R31 "TNPW060310K0BEEA" TNPW0603 5200.82,457 r180 top value=10.0k
R34 "CRCW06035K10JNEA" 0603L 2904,1926 r270 top value=5.1k
R36 "ERJ-6GEY0R00V" 0805L 4900.82,805 r180 top value=0
R37 "CSR1206FK30L0" 1206L 4154,2753 r90 top value=0.03
R41 "CRCW06035K10JNEA" 0603L 4582,3078 r90 top value=5.1k
R43 "CRCW060310K0JNEA" 0603L 2913.23,1705 r270 top value=10k
R44 "CRCW060368K0FKEA" FP-CRCW060368K0FKEA_0603-MFG 2914.23,1609 r270 top value=68k
R45 "CRCW040220K0FKED" 0402L 3862,2831 r270 top value=20.0k
R46 "CRCW060349K9FKEA" 0603L 4225,1641 r270 top value=49.9k
R47 "CRCW06030000Z0EA" 0603L 3953.26,1532.14 r90 top value=0
R48 "ERJ-3GEY0R00V" 0603L 5630.82,495.56 r90 top value=0
R49 "ERJ-3GEY0R00V" 0603L 5730.82,493 r90 top value=0
R50 "ERJ-3GEY0R00V" 0603L 5830.82,494 r90 top value=0
R51 "ERJ-3GEY0R00V" 0603L 5834.82,2186 r90 top value=0
R52 "CRCW060310R2FKEA" 0603L 4169.56,1846 r270 top value=10.2
R53 "CRCW06034K99FKEA" 0603L 4172.56,1695 r270 top value=4.99k
R54 "ERJ-3GEY0R00V" 0603L 2301,1654.44 r0 top value=0
R55 "CRCW060310R2FKEA" 0603L 4113.56,1848 r270 top value=10.2
R56 "CRCW06034K99FKEA" 0603L 4113.56,1695 r270 top value=4.99k
R57 "CRCW060349K9FKEA" 0603L 4060.56,1693 r90 top value=49.9k
R58 "CRCW060349K9FKEA" 0603L 3814.26,1639.14 r270 top value=49.9k
R59 "CRCW060310R2FKEA" 0603L 3865.26,1846.14 r270 top value=10.2
R60 "CRCW06034K99FKEA" 0603L 3867.26,1695.14 r270 top value=4.99k
R61 "CRCW060310R2FKEA" 0603L 3920.26,1846.14 r270 top value=10.2
R62 "CRCW06034K99FKEA" 0603L 3920.26,1695.14 r270 top value=4.99k
R63 "CRCW060349K9FKEA" 0603L 3973.26,1695.14 r90 top value=49.9k
R64 "CRCW060349K9FKEA" 0603L 4455,1643 r270 top value=49.9k
R65 "CRCW060310R2FKEA" 0603L 4414,1854 r270 top value=10.2
R66 "CRCW06034K99FKEA" 0603L 4402.56,1699 r270 top value=4.99k
R67 "CRCW060310R2FKEA" 0603L 4361,1853.56 r270 top value=10.2
R68 "CRCW06034K99FKEA" 0603L 4348.56,1699 r270 top value=4.99k
R69 "CRCW060349K9FKEA" 0603L 4295.56,1699 r90 top value=49.9k
R70 "CRCW0805330RFKEAC" 0805L 5483.82,1015 r90 top value=330
R71 "CRCW0805330RFKEAC" 0805L 5656.82,1021 r90 top value=330
R72 "CRCW0805330RFKEAC" 0805L 5730.82,1020 r90 top value=330
R73 "CRCW0603100KFKEA" 0603L 4273.26,1543.14 r90 top value=100k
R74 "CRCW0603100KFKEA" 0603L 4326.26,1542.14 r270 top value=100k
R75 "RC0603FR-07100RL" 0603L 5410.59,2558.59 r180 top value=100
R76 "RC0603FR-07100RL" 0603L 5610.59,2556.59 r180 top value=100
R77 "RC0603FR-07100RL" 0603L 5759.56,2564 r0 top value=100
R78 "ERJ-3GEY0R00V" 0603L 5458.82,1129 r90 top value=0
R79 "ERJ-3GEY0R00V" 0603L 5511.82,1128 r90 top value=0
R91 "RC1206FR-07332KL" 1206 3047,4453 r270 top value=332k
R92 "RC1206FR-07332KL" 1206 5023.3,4936 r90 top value=332k
R93 "RC1206FR-07332KL" 1206 5474,4939 r90 top value=332k
R94 "RC1206FR-07332KL" 1206 5932,4941 r90 top value=332k
R98 "RC1206FR-07332KL" 1206 3048,4673.54 r270 top value=332k
R99 "RC0603FR-078K2L" 0603 5004,5710 r180 top value=8.20k
R100 "RC0603FR-078K2L" 0603 5004.44,5634 r180 top value=8.20k
R101 "RC0603FR-078K2L" 0603 5074,4310 r90 top value=8.20k
R102 "RC0603FR-078K2L" 0603 4995,4311.53 r90 top value=8.20k
R103 "RC0603FR-078K2L" 0603 5450.27,4311.54 r90 top value=8.20k
R104 "RC0603FR-078K2L" 0603 5553.69,4311.54 r90 top value=8.20k
R105 "RC0603FR-078K2L" 0603 5981,4313 r90 top value=8.20k
R106 "RC0603FR-078K2L" 0603 5881,4312 r90 top value=8.20k
R107 "CRCW080520K0FKEA" 0805L 5512.82,854 r180 top value=20.0k
R108 "CRCW080520K0FKEA" 0805L 5629.93,854 r0 top value=20.0k
R109 "CRCW080520K0FKEA" 0805L 5745.82,852 r180 top value=20.0k
R110 "RC1206FR-07332KL" 1206 5023.3,4709.83 r90 top value=332k
R111 "RC1206FR-07332KL" 1206 5473,4713.88 r90 top value=332k
R112 "RC1206FR-07332KL" 1206 5931,4713 r90 top value=332k
R113 "RC1206FR-07332KL" 1206 3048,4895 r270 top value=332k
R116 "RC1206FR-07332KL" 1206 5023,4489.53 r90 top value=332k
R117 "CRCW06035K10JNEA" 0603L 4891.82,258.56 r90 top value=5.1k
R118 "CRCW060349K9FKEA" 0603L 3378,1701.44 r90 top value=49.9k
R119 "CRCW06032K67FKEA" 0603L 3378,1598.44 r90 top value=2.67k
R120 "RC0603FR-07100RL" 0603L 5435.7,444.13 r90 top value=100
R121 "RC1206FR-07330KL" 1206 1529,4096 r180 top value=330k
R122 "RC1206FR-07330KL" 1206 1954.41,4095 r180 top value=330k
R123 "CRCW06035K10JNEA" 0603L 5146.82,253 r90 top value=5.1k
R124 "CRCW06035K10JNEA" 0603L 5015,2992 r270 top value=5.1k
R125 "CRCW06035K10JNEA" 0603L 5068,2992 r270 top value=5.1k
R126 "CRCW06035K10JNEA" 0603L 5124,2992.44 r270 top value=5.1k
R127 "CRCW06035K10JNEA" 0603L 4522,3076.38 r270 top value=5.1k
R128 "CRCW040220K0FKED" 0402L 3861,2905 r180 top value=20.0k
R129 "ERJ-2RKF2001X" 0402L 4327,2564 r270 top value=2.00k
R130 "RC1206FR-07332KL" 1206 5475,4485 r90 top value=332k
R134 "RC1206FR-07332KL" 1206 5932,4489 r90 top value=332k
R135 "ERJ-3GEY0R00V" 0603L 5051.7,494.69 r90 top value=0
R137 "ERJ-3GEY0R00V" 0603L 5382.7,493.13 r90 top value=0
R138 "ERJ-3GEY0R00V" 0603L 5721.64,2198.03 r90 top value=0
R139 "ERJ-3GEY0R00V" 0603L 5562.7,2498.69 r180 top value=0
RT1 "CL-40" Thermistor_CL-40 1013,4507 r270 top value=5
RV1 "B72210P2351K101" FP-B72210P2351K101_RADIAL-MFG 1705,5182 r180 top
SH-J1 "SNT-100-BK-G" SNT-100-BK-G 4042.77,1171.44 r180 top value=1x2
SH-J2 "SNT-100-BK-G" SNT-100-BK-G 2117,1129 r180 top value=1x2
SH-J3 "SNT-100-BK-G" SNT-100-BK-G 5746,5404 r180 top value=1x2
SH-J4 "SNT-100-BK-G" SNT-100-BK-G 3073,1877 r180 top value=1x2
SH-J5 "SNT-100-BK-G" SNT-100-BK-G 3521,1848 r180 top value=1x2
TP1 "OUTA" Keystone5000 3512,4086 r90 top
TP2 "OUTB" Keystone5000 4051,4087.68 r90 top
TP3 "OUTC" Keystone5000 4592,4087 r90 top
TP4 "K_OUTA" Keystone5000 3342.08,4213.18 r90 top
TP5 "K_LS_D" Keystone5000 3364.77,4340.4 r90 top
TP6 "K_OUTB" Keystone5000 3894.61,4348.54 r180 top
TP7 "K_OUTB" Keystone5000 3816.29,4245.27 r180 top
TP8 "INHA" Testpoint_Keystone_Miniature 4773.59,2701.59 r0 top
TP9 "K_OUTC" Keystone5000 4838.99,3661.43 r90 top
TP10 "K_LS_D" Keystone5000 4821.5,3468 r90 top
TP11 "GND" Harwin_D3082-05 2900,433 r180 top
TP12 "PGND" Harwin_D3082-05 754,1956 r270 top
TP13 "PGND" Harwin_D3082-05 569,1965 r270 top
TP14 "SNB" Keystone5002 4169.19,2134 r270 top
TP16 "GND" Keystone5001 6227,286 r90 top
TP17 "PGND" Keystone5001 4005.73,2444 r90 top
TP18 "INHB" Testpoint_Keystone_Miniature 5177.59,2698.59 r0 top
TP19 "LDO_IN" Keystone5009 2168,1360 r90 top
TP20 "INLB" Testpoint_Keystone_Miniature 5383.59,2699.59 r180 top
TP21 "INLA" Testpoint_Keystone_Miniature 4974.59,2697.59 r180 top
TP22 "INHC" Testpoint_Keystone_Miniature 5584.59,2699.59 r180 top
TP23 "INLC" Testpoint_Keystone_Miniature 5785.59,2702.59 r0 top
TP24 "SLEW" Testpoint_Keystone_Miniature 3126,1424 r180 top
TP26 "3.3V" Keystone5002 2539,1614.52 r90 top
TP29 "BOOTA" Keystone5000 3684,4449 r90 top
TP30 "+5V" Keystone5009 4753.82,739 r180 top
TP31 "SNA" Keystone5002 3812.26,1973.14 r270 top
TP32 "BOOTB" Keystone5000 4208,4357 r90 top
TP33 "BK_PWR" Keystone5009 1920,1213 r0 top
TP34 "BOOTC" Keystone5000 4435,4293 r90 top
TP35 "VM" Keystone5000 887,3479 r90 top
TP36 "ILIMIT" Keystone5002 3537,1654 r90 top
TP37 "AMPIN+" Keystone5002 4636.51,2445.01 r90 top
TP38 "AMPIN-" Keystone5002 4636,2285 r90 top
TP39 "AMPOUT" Keystone5002 3659,1561 r180 top
TP40 "K_VM" Keystone5000 2880,3707 r90 top
TP41 "K_VM" Keystone5000 2656,3703 r90 top
TP42 "GVDD" Keystone5009 1661,1979 r0 top
TP43 "ENABLE" Testpoint_Keystone_Miniature 2850,1325 r180 top
TP44 "BRAKE" Keystone5002 5339.09,3012.11 r90 top
TP45 "nFAULT" Testpoint_Keystone_Miniature 4893,3048 r90 top
TP46 "VTEMP" Keystone5002 4742.82,388 r90 top
TP47 "SLA" Keystone5002 3973.26,1965.14 r90 top
TP48 "SLB" Keystone5002 4083.96,2037.14 r90 top
TP49 "SLC" Keystone5002 4251.26,2033.14 r270 top
TP50 "K_GVDD" Keystone5009 3263,2037 r0 top
TP52 "HALL_EXT" Keystone5002 6069,5406 r90 top
TP53 "HALL_PWR" Keystone5002 6072,5259 r90 top
TP54 "SNC" Keystone5002 4421.26,2036.14 r90 top
TP55 "ISENA" Keystone5002 5534.82,1330 r180 top
TP56 "ISENB" Keystone5002 5663.82,1328 r180 top
TP57 "ISENC" Keystone5002 5792.82,1322 r180 top
U1 "DRV7308HRENR" REN0065A-MFG 4037.07,3196.38 r90 top
U2 "TLV74133PDBVR" DBV0005A_N 2314,1442.9 r90 top
U3 "TPD4S009DCKR" DCK0006A_N 5153.09,1263.38 r0 top
U4 "LMR51420YFDDCR" DDC0006A-MFG 2218.7,753.67 r270 top
U5 "TLV9064IPWR" PW0014A_N 4150.26,1362.14 r0 top
ZZ1 "This Assembly Note is for PCB labels only" AssemblyNoteLabel 213.77,7380.7 r0 top
ZZ2 "These assemblies are ESD sensitive, ESD precautions shall be observed." AssemblyNote 213.77,7271.82 r0 top
ZZ3 "These assemblies must be clean and free from flux and all contaminants. Use of no clean flux is not acceptable." AssemblyNote 213.77,7183.26 r0 top
ZZ4 "These assemblies must comply with workmanship standards IPC-A-610 Class 2, unless otherwise specified." AssemblyNote 213.77,7094.7 r0 top

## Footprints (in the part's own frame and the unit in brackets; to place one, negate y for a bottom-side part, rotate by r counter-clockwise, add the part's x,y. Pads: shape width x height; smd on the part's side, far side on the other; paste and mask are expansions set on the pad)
381LQ_J02 [mm] "TH, 2-Leads, Dia 25mm, Pin Spacing 10mm"
  rrect50% 3x3 hole 2: 1(-5,0)
  round 3 hole 2: 2(5,0)
  body extent -13,-13 13.01,13, height 32.01
0402L [mm] "0402 from SM-752 data"
  rect 0.6x0.5 smd: 1(-0.5,0) 2(0.5,0)
  body extent -0.55,-0.3 0.55,0.3, height 0.6
0603 [mm] "0603 from SM-752 data"
  rect 1x0.95 smd: 1(-0.8,0) 2(0.8,0)
  silkscreen extent -1.52,-0.69 1.52,0.69, body extent -0.87,-0.47 0.87,0.47, height 1
0603L [mm] "0603 from SM-752 data"
  rect 0.8x0.85 smd: 1(-0.7,0) 2(0.7,0)
  silkscreen extent -0.07,-0.33 0.07,0.33, body extent -0.87,-0.47 0.87,0.47, height 1
0805_HV [mil] "0805 with 30mil clearance between pads"
  rect 50x63 smd: 1(-40,0) 2(40,0)
  silkscreen extent -74,-40 74,40, body extent -43,-29 43,29, height 57
0805L [mm] "0805 from SM-752 data"
  rect 1.1x1.4 smd: 1(-0.75,0) 2(0.75,0)
  body extent -1.1,-0.72 1.1,0.72, height 1.45
1206 [mm] "1206 from SM-752 data"
  rect 1.3x1.85 smd: 1(-1.45,0) 2(1.45,0)
  silkscreen extent -2.4,-1.21 2.4,1.21, body extent -1.7,-0.9 1.7,0.9, height 1.35
1206_180L [mm] "1206_180"
  rect 1.1x1.75 smd: 1(-1.35,0) 2(1.35,0)
  silkscreen extent -0.4,-0.77 0.4,0.77, body extent -1.75,-0.95 1.75,0.95, height 1.8
1206L [mm] "1206 from SM-752 data"
  rect 1.1x1.75 smd: 1(-1.35,0) 2(1.35,0)
  silkscreen extent -0.4,-0.77 0.4,0.77, body extent -1.7,-0.9 1.7,0.9, height 1.35
1210_270L [mm] "1210"
  rect 1.1x2.6 smd: 1(-1.35,0) 2(1.35,0)
  silkscreen extent -0.4,-1.2 0.4,1.2, body extent -1.7,-1.35 1.7,1.35, height 2.7
1808 [mm] "Chip Capacitor, Body 4.6x2.0mm, IPC Medium Density"
  rect 1.4x2.3 smd: 1(-2.1,0) 2(2.1,0)
  silkscreen extent -3.1,-1.45 3.1,1.45, body extent -2.47,-1.2 2.47,1.2, height 2.03
1812_170_HighSpeed [mm] "Wurth recommended land pattern"
  rrect7% 1.4x3 smd: 1(-2.45,0) 2(2.45,0)
  silkscreen extent -1.5,-1.5 1.5,1.5, body extent -2.25,-1.6 2.25,1.6, height 1.51
AssemblyNote [mil] "Assembly Note"
AssemblyNoteLabel [mil] "Assembly Note for PCB Labels"
B32922_14.5mm [mm] "Epcos film capacitors, 15mm spacing"
  rect 1.5x1.5 hole 1: 1(-7.5,0)
  round 1.5 hole 1: 2(7.5,0)
  silkscreen extent -9,-4.25 9,4.25, body extent -9,-4.25 9,4.25, height 14.5
BT_1000x1250 [mm] "Nichicon"
  rect 1.35x1.35 hole 0.85 paste+0: 1(-2.5,0)
  round 1.35 hole 0.85 paste+0: 2(2.5,0)
  silkscreen extent -5.58,-5.4 5.4,5.4, body extent -5.36,-5.39 5.39,5.39, height 14.51
BuildingFastener_MPMS_003_0005_PH [mil] "MACHINE SCREW PAN PHILLIPS M3"
  round 1 on Mech3: 0(0,0)
  body extent -118,-118 118,118, height 93
CE_Mark_5mm [mil] "Minimum text height for CE Mark"
  silkscreen extent -138,-98 138,98
Chemi-Con_1000x2000 [mm] "TH, 2-Leads, Body 10x20mm, Pin Spacing 5mm"
  rect 1.35x1.35 hole 0.85: 1(-2.5,0)
  round 1.35 hole 0.85: 2(2.5,0)
  silkscreen extent -5.25,-5.25 5.25,5.25, body extent -5.25,-5.25 5.25,5.25, height 21.5
CTE_CT3151SP-0 [mm] "Banana Jack Insul Nylon Black, R/A, TH"
  round 2.1 hole 1.6: 1(18.898,-2.54) 1(18.898,2.54) 1(23.978,-2.54) 1(23.978,2.54)
  silkscreen extent 0.44,-6.75 18.02,6.75, body extent -3.06,-6.7 24.64,6.8, height 14.37
CTE_CT3151SP-2 [mm] "Banana Jack Insul Nylon Red, R/A, TH"
  round 2.1 hole 1.6: 1(18.898,-2.54) 1(18.898,2.54) 1(23.978,-2.54) 1(23.978,2.54)
  silkscreen extent 0.44,-6.75 18.02,6.75, body extent -3.06,-6.75 24.64,6.75, height 14.37
DBV0005A_N [mm] "SOT23, 5-Leads, Body 2.9x1.6mm, Pitch 0.95mm, Lead Span 2.8mm, IPC Medium Density"
  rrect17% 1x0.6 smd: 1(-1.375,0.95) 2(-1.375,0) 3(-1.375,-0.95) 4(1.375,-0.95) 5(1.375,0.95)
  silkscreen extent -0.25,-1.55 0.25,1.55, body extent -1.42,-1.46 1.42,1.46, height 1.09
DCK0006A_N [mm] "SOT23, 6-Leads, Body 2x1.3mm, Pitch 0.65mm, Lead Span 2.1mm, IPC Medium Density"
  rrect25% 0.85x0.4 smd: 1(-1.125,0.65) 2(-1.125,0) 3(-1.125,-0.65) 4(1.125,-0.65) 5(1.125,0) 6(1.125,0.65)
  silkscreen extent -1.5,-1.09 0.51,1.09, body extent -1.14,-1 1.14,1, height 0.95
DDC0006A-MFG [mm]
  rrect17% 1.1x0.6 smd paste+0 mask+0: 1(-1.35,0.95) 2(-1.35,0) 3(-1.35,-0.95) 4(1.35,-0.95) 5(1.35,0) 6(1.35,0.95)
  silkscreen extent -2.57,-1.53 0.42,1.53, body extent -2,-1.63 2,1.63, height 0.25
FCC_disclaimer [mil]
FCI_68001-403HLF [mm] "Header, 2.54mm, 3x1, TH"
  rect 1.55x1.55 hole 1.02: 1(-2.54,0)
  round 1.55 hole 1.02: 2(0,0) 3(2.54,0)
  silkscreen extent -3.81,-1.21 3.81,1.5, body extent -3.81,-1.21 3.81,1.21, height 8.38
Fiducial10-20 [mm]
  round 1 smd mask+0.5: 1(0,0)
  Top Layer keep-out circle w1.178: c0,0 r0.5
FP-885012206069_0603-MFG [mm]
  rrect13% 0.8x0.8 smd paste+0 mask+0: 1(-0.75,0) 2(0.75,0)
  body extent -1.25,-0.55 1.25,0.55, height 0.25
FP-B72210P2351K101_RADIAL-MFG [mm]
  rrect6% 1.55x1.55 hole 1 paste-1000 mask+0: 1(-3.75,1.95)
  round 1.55 hole 1 paste-1000 mask+0: 2(3.75,-1.95)
  body extent -6.35,-3.45 6.35,3.45, height 0.25
FP-CRCW060368K0FKEA_0603-MFG [mm]
  rrect13% 0.75x1 smd paste+0 mask+0: 1(-0.75,0) 2(0.75,0)
  silkscreen extent -0.8,-0.9 0.8,0.9, body extent -1.22,-0.6 1.22,0.6, height 0.25
FP-VJ2225Y104KXGAT_2225-IPC_A [mil]
  rrect6% 69.04x263.98 smd paste+0 mask+0: 1(-102.19,0) 2(102.19,0)
  silkscreen extent -56,-132 56,132, body extent -156,-152 156,152, height 10
FUSE_0443 [mm] "LITTELFUSE"
  rect 3.25x3.43 smd: 1(-4.675,0) 2(4.675,0)
  silkscreen extent -2.7,-1.7 2.7,1.7, body extent -5.05,-1.56 5.05,1.56, height 3.12
GBU [mm] "Comchip / Diodes Inc diode bridge"
  round 2 hole 1.5: 1(-7.62,0) 2(-2.54,0) 3(2.54,0) 4(7.62,0)
  silkscreen extent -11.15,-2.28 11.15,1.28, body extent -11.15,-2.28 11.15,1.28, height 21.55
Harwin_D3082-05 [mm] "Shorting Plug, 10.16mm spacing, TH"
  round 1.8 hole 1.3: 1(-5.08,0) 2(5.08,0)
  silkscreen extent -3.9,-0.53 3.9,0.53, body extent -5.6,-0.52 5.61,0.52, height 6.63
IEC_HighVoltage_Small [mil]
  silkscreen extent -107,-88 107,97
IEC_HotSurface_Small [mil]
  silkscreen extent -107,-93 107,92
Keystone5000 [mil] "For Keystone 500x miniature loop terminals"
  round 80 hole 40: 1(0,0)
  silkscreen extent -52,-52 52,52, body extent -49,-49 49,49, height 182
Keystone5001 [mil] "For Keystone 500x miniature loop terminals"
  round 80 hole 40: 1(0,0)
  silkscreen extent -52,-52 52,52, body extent -49,-49 49,49, height 182
Keystone5002 [mil] "For Keystone 500x miniature loop terminals"
  round 80 hole 40: 1(0,0)
  silkscreen extent -52,-52 52,52, body extent -49,-49 49,49, height 182
Keystone5009 [mil] "Keystone Compact loops"
  round 87 hole 63: 1(0,0)
  silkscreen extent -70,-70 70,70, body extent -63,-63 62,63, height 225
Keystone24438 [mil] "Standoff, Aluminium, M3x0.5mm, L 25 mm"
  round 1 on Mech4: 0(0,0)
  body extent -98,-114 98,114, height 984
LED_LTST-C170_Red [mm] "LITE-ON"
  rect 1.2x1.2 smd: 1(-1.05,0) 2(1.05,0)
  silkscreen extent -1.6,-1 2.2,1, body extent -1.05,-0.67 1.05,0.67, height 1.1
LTST-C170KFKT_Orange [mm] "LITE-ON"
  rect 1.2x1.2 smd: 1(-1.05,0) 2(1.05,0)
  silkscreen extent -1.6,-1 2.2,1, body extent -1.05,-0.67 1.05,0.67, height 1.1
LTST-C170KGKT_Green [mm] "LITE-ON"
  rect 1.2x1.2 smd: 1(-1.05,0) 2(1.05,0)
  silkscreen extent -1.6,-1 2.2,1, body extent -1.05,-0.67 1.05,0.67, height 1.1
MTGP_M3_PanHead [mm] "M3Mounting Hole, Plated, for Pan Head"
  round 6.8 hole 3.3: 1(0,0)
Net-Tie_10mil [mil] "10mil net tie, no solder mask opening, no solder paste"
  rect 10x10 smd paste-5 mask-5: 1(-10,0) 2(10,0)
  Top Layer region: -6,5 6,5 6,-5 -6,-5
Net-Tie_10milWide_30milLong [mil] "10mil net tie, no solder mask opening, no solder paste"
  rect 30x10 smd paste-5 mask-5: 1(-15,0) 2(15,0)
Net-Tie_50milWide_30milLong [mil] "50mil net tie, no solder mask opening, no solder paste"
  rect 30x50 smd paste-20 mask-20: 1(-15,0) 2(15,0)
On-Shore_OSTVN02A150 [mm] "Terminal Block, 2.54mm, 2-pole, Brass, TH"
  rect 1.8x1.8 hole 1.3: 1(-1.27,0)
  round 1.8 hole 1.3: 2(1.27,0)
  silkscreen extent -3.1,-3.25 2.77,3.25, body extent -2.77,-3.25 2.77,3.25, height 8.51
Phoenix_1792892 [mm] "Terminal Block, 5mm, 5x1, R/A, TH"
  rrect50% 1.7x1.7 hole 1.2: 1(-10,0)
  round 1.7 hole 1.2: 2(-5,0) 3(0,0) 4(5,0) 5(10,0)
  silkscreen extent -12.8,-4.95 12.5,5.55, body extent -12.5,-4.95 12.5,5.55, height 13.6
Phoenix_1904150 [mm] "TH, 3-Leads, Body 28.56x16mm, Pitch 9.52mm"
  rect 1.8x1.8 hole 1.3: 1(-9.52,3.1)
  round 1.8 hole 1.3: 2(0,3.1) 3(9.52,3.1)
  silkscreen extent -14.8,-8 14.85,8, body extent -14.28,-8 14.85,8, height 22
PW0014A_N [mm] "TSOP, 14-Leads, Body 5x4.4mm, Pitch 0.65mm, IPC Medium Density"
  oval 1.4x0.45 smd: 1(-2.95,1.95) 2(-2.95,1.3) 3(-2.95,0.65) 4(-2.95,0) 5(-2.95,-0.65) 6(-2.95,-1.3) 7(-2.95,-1.95) 8(2.95,-1.95) 9(2.95,-1.3) 10(2.95,-0.65) 11(2.95,0) 12(2.95,0.65) 13(2.95,1.3) 14(2.95,1.95)
  silkscreen extent -3.4,-2.55 1.85,2.55, body extent -3.21,-2.5 3.21,2.5, height 1
REN0065A-MFG [mm]
  rrect22% 0.6x0.446 smd paste+0 mask+0: 1(-5.9,5.598) 23(-5.9,-5.598)
  rrect40% 0.6x0.25 smd paste+0 mask+0: 2(-5.9,5) 3(-5.9,4.5) 4(-5.9,4) 5(-5.9,3.5) 6(-5.9,3) 7(-5.9,2.5) 17(-5.9,-2.5) 18(-5.9,-3) 19(-5.9,-3.5) 20(-5.9,-4) 21(-5.9,-4.5) 22(-5.9,-5) 40(5.9,-3.916) 41(5.9,-3.416) 43(5.9,-0.5) 44(5.9,0) 48(5.9,3.416) 49(5.9,3.916)
  rrect40% 0.6x0.25 smd paste-1000 mask-1000: 8(-5.9,2) 9(-5.9,1.5) 10(-5.9,1) 11(-5.9,0.5) 12(-5.9,0) 13(-5.9,-0.5) 14(-5.9,-1) 15(-5.9,-1.5) 16(-5.9,-2) 38(5.9,-4.916) 39(5.9,-4.416) 45(5.9,0.5) 46(5.9,1) 47(5.9,1.5) 50(5.9,4.416) 51(5.9,4.916)
  rrect40% 0.25x1.375 smd paste-1000 mask+0: 24(-5.225,-5.513) 25(-4.725,-5.513) 26(-4.225,-5.513) 27(-3.725,-5.513) 28(-3.225,-5.513) 29(-2.725,-5.513) 60(-2.725,5.513) 61(-3.225,5.513) 62(-3.725,5.513) 63(-4.225,5.513) 64(-4.725,5.513) 65(-5.225,5.513)
  rrect40% 0.25x0.45 smd paste+0 mask-1000: 30(-0.45,-5.975) 31(0.05,-5.975) 58(0.05,5.975) 59(-0.45,5.975)
  rrect22% 0.5x0.455 smd paste+0 mask-1000: 32(2.65,-5.973) 36(4.9,-5.973) 53(4.9,5.973) 57(2.65,5.973)
  rrect40% 0.25x0.455 smd paste+0 mask-1000: 33(3.275,-5.973) 34(3.775,-5.973) 35(4.275,-5.973) 54(4.275,5.973) 55(3.775,5.973) 56(3.275,5.973)
  rrect18% 0.6x0.55 smd paste+0 mask+0: 37(5.9,-5.566) 42(5.9,-1.15) 52(5.9,5.566)
  rrect5% 1.975x1.94 smd paste-1000 mask+0: 66(-4.221,3.465) 70(-4.221,-3.465)
  rrect8% 2.601x1.25 smd paste-1000 mask+0: 67(-4.099,1.475) 69(-4.099,-1.475)
  rrect8% 2.601x1.2 smd paste-1000 mask+0: 68(-4.099,0)
  rrect4% 2.41x6 smd paste-1000 mask+0: 71(-1.233,0)
  rrect3% 3.278x3.175 smd paste-1000 mask+0: 72(3.711,0)
  rrect29% 0.7x1.35 smd paste-1000 mask-1000: ""(-5.9,-1.5) ""(-5.9,0) ""(-5.9,1.5) ""(5.9,1)
  rrect24% 0.85x1.301 smd paste-1000 mask-1000: ""(-0.2,5.6) ""(-0.2,-5.6)
  rrect6% 3.378x3.097 smd paste-1000 mask-1000: ""(3.711,-4.702) ""(3.711,4.702)
  rrect29% 0.7x0.85 smd paste-1000 mask-1000: ""(5.9,-4.666) ""(5.9,4.666)
  silkscreen extent -6.87,-6.43 6.43,6.43, body extent -6.35,-6.35 6.35,6.35, height 0.25
Samtec_SSQ-110-03-x-D [mm] "Receptacle, 2.54mm, 10x2, TH"
  rect 1.55x1.55 hole 1.02: 1(-11.43,1.27)
  round 1.55 hole 1.02: 2(-11.43,-1.27) 3(-8.89,1.27) 4(-8.89,-1.27) 5(-6.35,1.27) 6(-6.35,-1.27) 7(-3.81,1.27) 8(-3.81,-1.27) 9(-1.27,1.27) 10(-1.27,-1.27) 11(1.27,1.27) 12(1.27,-1.27) 13(3.81,1.27) 14(3.81,-1.27) 15(6.35,1.27) 16(6.35,-1.27) 17(8.89,1.27) 18(8.89,-1.27) 19(11.43,1.27) 20(11.43,-1.27)
  silkscreen extent -12.95,-2.48 12.95,3, body extent -12.95,-2.48 12.95,2.48, height 8.51
SNT-100-BK-G [mil] "Samtec STEP model"
  round 1 on Mech3: 0(0,0)
  body extent -100,-50 100,50, height 344
SOD-323 [mm] "NXP recommended land pattern"
  rect 0.6x0.6 smd paste-0.05: 1(-1.1,0) 2(1.1,0)
  silkscreen extent -2.06,-0.86 1.53,0.86, body extent -1.3,-0.67 1.3,0.68, height 1.1
Testpoint_Keystone_Miniature [mil] "Miniature SMT test point"
  rect 135x70 smd: 1(0,0)
  silkscreen extent -78,-46 78,45, body extent -52,-20 52,20, height 61
Thermistor_CL-40 [mil] "GE"
  round 80 hole 52: 1(-164,110) 2(164,-110)
  silkscreen extent -402,-118 402,118, body extent -378,-127 388,127, height 804
TI_Stacked_Overlay_Small [mil]
  silkscreen extent -418,-98 418,98
TNPW0603 [mm] "Vishay"
  rect 0.5x0.9 smd: 1(-0.75,0) 2(0.75,0)
  silkscreen extent -0.2,-0.6 0.2,0.6, body extent -0.85,-0.47 0.85,0.47, height 0.55
TSW-102-07-G-S [mm] "Samtec 100mil, 1x2, 230 mil above insulator"
  rrect50% 1.65x1.65 hole 1.016: 1(-1.27,0)
  round 1.65 hole 1.016: 2(1.27,0)
  silkscreen extent -3.17,-1.27 2.54,1.27, body extent -2.54,-1.27 2.54,1.27, height 8.38
TSW-104-07-G-D [mm] "Samtec 100mil, 2x4, 230 mil above insulator"
  rrect6% 1.65x1.65 hole 1.016: 1(-3.81,-1.27)
  round 1.65 hole 1.016: 2(-3.81,1.27) 3(-1.27,-1.27) 4(-1.27,1.27) 5(1.27,-1.27) 6(1.27,1.27) 7(3.81,-1.27) 8(3.81,1.27)
  silkscreen extent -6.1,-2.54 5.08,2.54, body extent -5.08,-2.54 5.08,2.54, height 8.38
WCAP-CSGP_0603_L1.6W0.8H0.8_Reflow [mm] "Ceramic Capacitors, body 1.6x0.8mm"
  rect 0.8x0.8 smd: 1(-0.75,0) 2(0.75,0)
  body extent -0.8,-0.4 0.8,0.4, height 0.8
WCAP-CSGP_0603_L1.6W0.8H0.8_Wave [mm] "Ceramic Capacitors, 0603, body 1.6x0.8mm"
  rect 0.7x0.8 smd: 1(-0.85,0) 2(0.85,0)
  body extent -0.8,-0.4 0.8,0.4, height 0.8
WE-MAIA_3015 [mm] "SMD, 2-Leads, Body 3x3mm"
  rect 1.3x3.4 smd: 1(-1.05,0) 2(1.05,0)
  silkscreen extent -0.1,-1.6 0.1,1.6, body extent -1.6,-1.6 1.6,1.6, height 1.5
WEEE_Minimum [mil] "WEEElie bin"
  silkscreen extent -95,-172 99,104
WURTH_61300311121 [mm] "Header, 2.54mm, 3x1, TH"
  rrect50% 1.65x1.65 hole 1.15: 1(-2.54,0)
  round 1.65 hole 1.15: 2(0,0) 3(2.54,0)
  body extent -3.81,-1.27 3.81,1.27, height 8.54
